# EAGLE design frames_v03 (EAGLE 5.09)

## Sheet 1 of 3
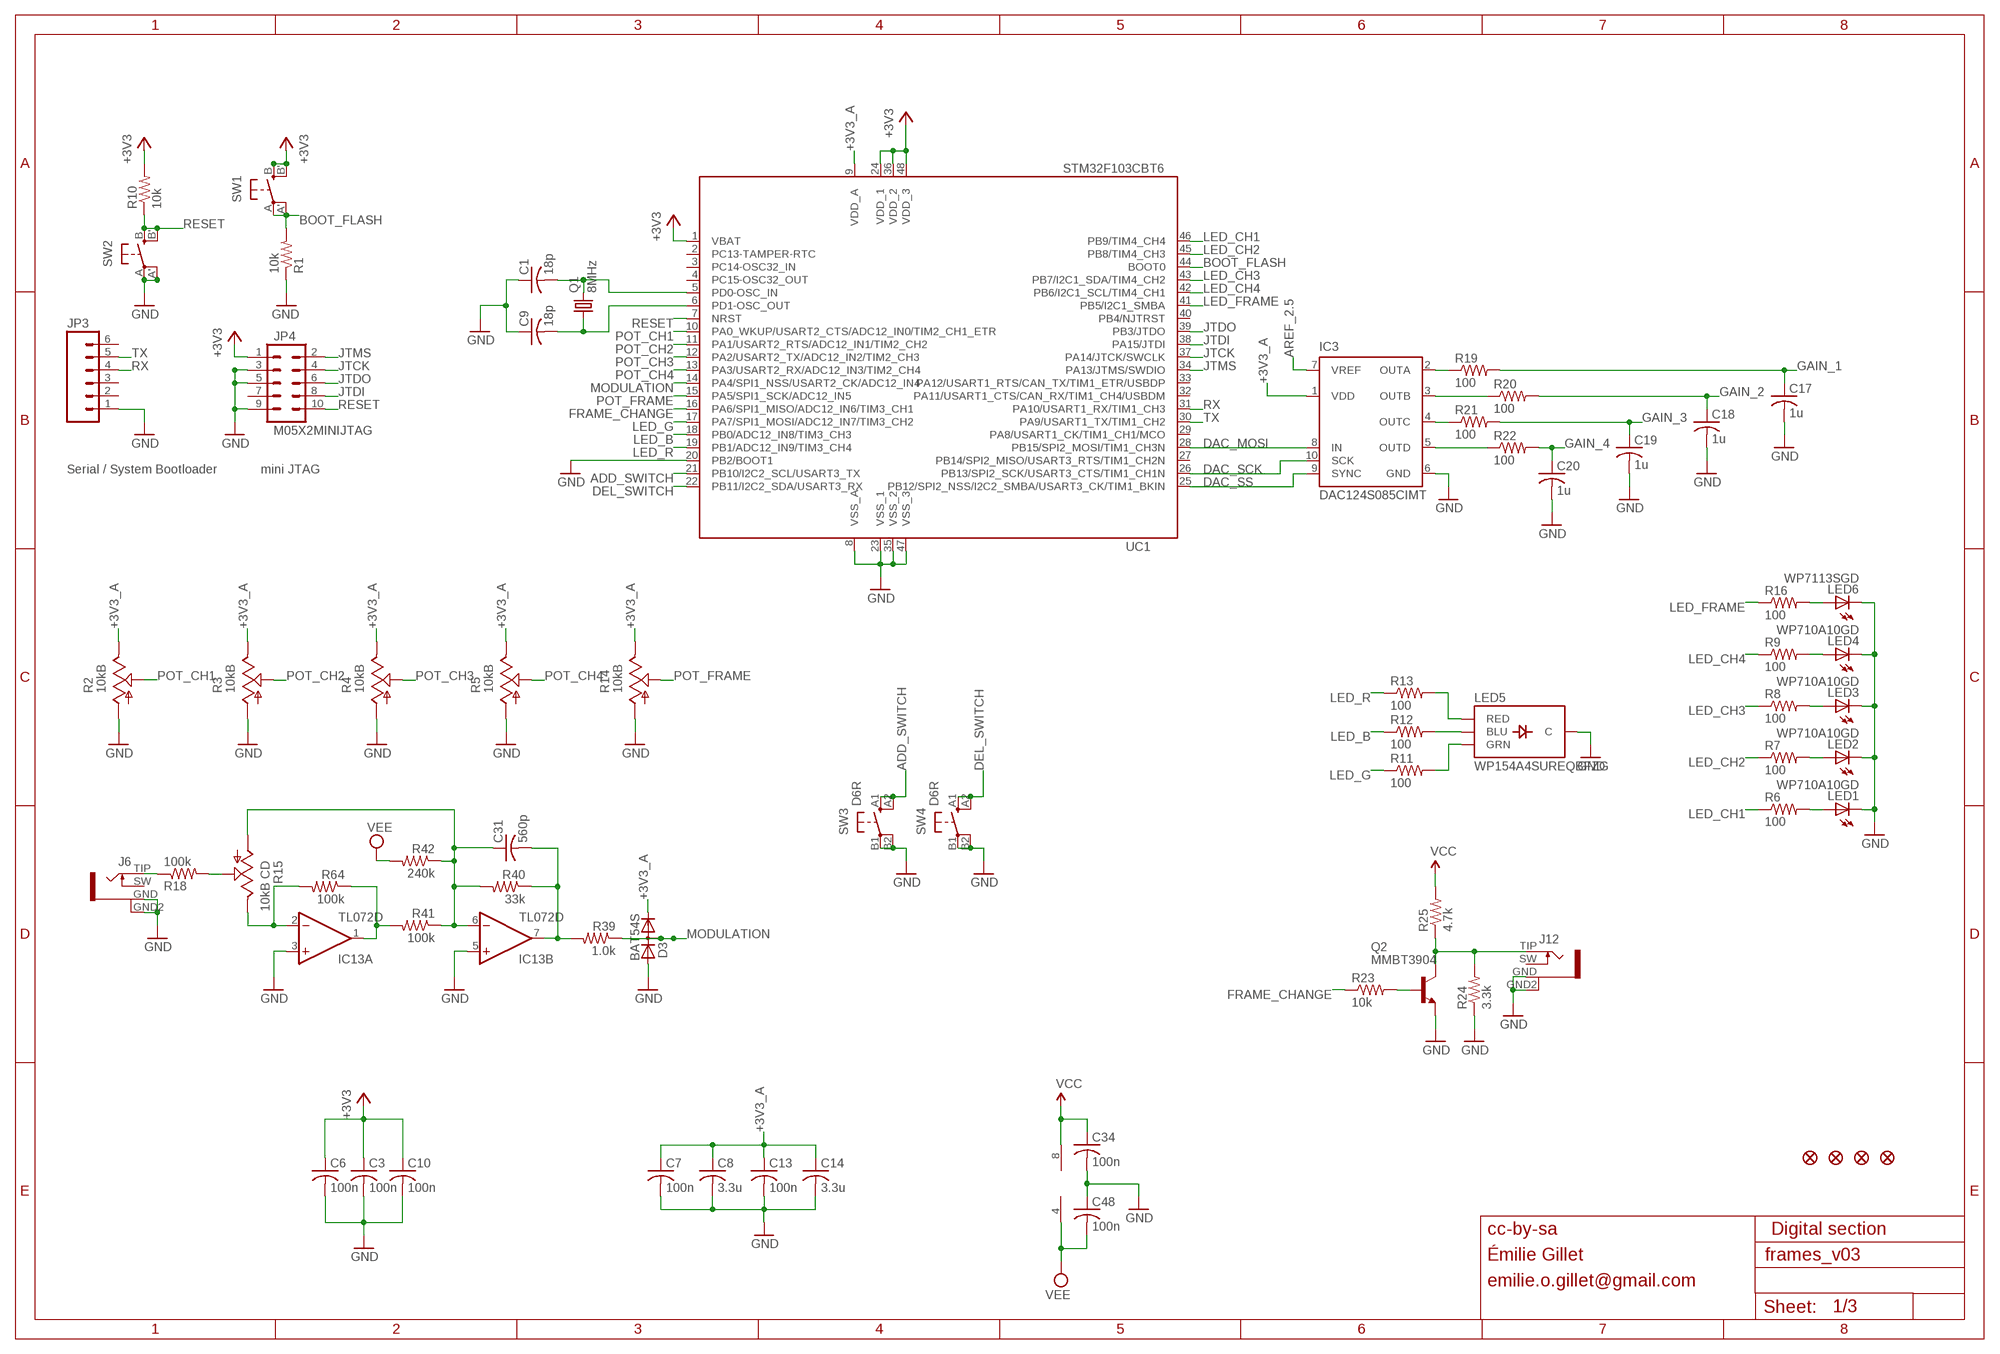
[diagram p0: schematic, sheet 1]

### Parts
C1  18p  C-USC0603  [C0603]
C3  100n  C-USC0603  [C0603]
C6  100n  C-USC0603  [C0603]
C7  100n  C-USC0603  [C0603]
C8  3.3u  C-USC0603  [C0603]
C9  18p  C-USC0603  [C0603]
C10  100n  C-USC0603  [C0603]
C13  100n  C-USC0603  [C0603]
C14  3.3u  C-USC0603  [C0603]
C17  1u  C-USC0603  [C0603]
C18  1u  C-USC0603  [C0603]
C19  1u  C-USC0603  [C0603]
C20  1u  C-USC0603  [C0603]
C31  560p  C-USC0603  [C0603]
C34  100n  C-USC0603  [C0603]
C48  100n  C-USC0603  [C0603]
D3  BAT54S  DIODE_2CACA-SOT23  [SOT23]
F1  FIDUCIAL1X2  [FIDUCIAL-1X2]
F2  FIDUCIAL1X2  [FIDUCIAL-1X2]
F3  FIDUCIAL1X2  [FIDUCIAL-1X2]
F4  FIDUCIAL1X2  [FIDUCIAL-1X2]
IC3  DAC124S085CIMT  [MSOP10]
IC13  TL072D  [SO08]
J6  PJ301WQP  [WQP_PJ_301BM]
J12  PJ301WQP  [WQP_PJ_301BM]
JP3  M06SIP  [1X06]
JP4  M05X2MINIJTAG  [2X5-1.27]
LED1  WP710A10GD  LED3MM  [LED3MM]
LED2  WP710A10GD  LED3MM  [LED3MM]
LED3  WP710A10GD  LED3MM  [LED3MM]
LED4  WP710A10GD  LED3MM  [LED3MM]
LED5  WP154A4SUREQBFZG  LED-TRICOLOR-THROUGHHOLE  [LED-TRICOLOR-THROUGHHOLE]
LED6  WP7113SGD  LED5MM  [LED5MM]
Q1  8MHz  CRYSTALHC49UP  [HC49UP]
Q2  MMBT3904  MMBT3904LT1-NPN-SOT23-BEC  [SOT23-BEC]
R1  10k  R-US_R0603  [R0603]
R2  10kB  POT_USVERTICAL_PS  [ALPS_POT_VERTICAL_PS]
R3  10kB  POT_USVERTICAL_PS  [ALPS_POT_VERTICAL_PS]
R4  10kB  POT_USVERTICAL_PS  [ALPS_POT_VERTICAL_PS]
R5  10kB  POT_USVERTICAL_PS  [ALPS_POT_VERTICAL_PS]
R6  100  R-US_R0603  [R0603]
R7  100  R-US_R0603  [R0603]
R8  100  R-US_R0603  [R0603]
R9  100  R-US_R0603  [R0603]
R10  10k  R-US_R0603  [R0603]
R11  100  R-US_R0603  [R0603]
R12  100  R-US_R0603  [R0603]
R13  100  R-US_R0603  [R0603]
R14  10kB  POT_USVERTICAL_PS  [ALPS_POT_VERTICAL_PS]
R15  10kB CD  POT_USVERTICAL_PS  [ALPS_POT_VERTICAL_PS]
R16  100  R-US_R0603  [R0603]
R18  100k  R-US_R0603  [R0603]
R19  100  R-US_R0603  [R0603]
R20  100  R-US_R0603  [R0603]
R21  100  R-US_R0603  [R0603]
R22  100  R-US_R0603  [R0603]
R23  10k  R-US_R0603  [R0603]
R24  3.3k  R-US_R0603  [R0603]
R25  4.7k  R-US_R0603  [R0603]
R39  1.0k  R-US_R0603  [R0603]
R40  33k  R-US_R0603  [R0603]
R41  100k  R-US_R0603  [R0603]
R42  240k  R-US_R0603  [R0603]
R64  100k  R-US_R0603  [R0603]
SW1  EVQQ2  [EVQ-Q2]
SW2  EVQQ2  [EVQ-Q2]
SW3  D6R  [D6R]
SW4  D6R  [D6R]
UC1  STM32F103CBT6  STM32F103CB  [LQFP48]

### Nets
+3V3: C3.1 C6.1 C10.1 JP4.1 R10.2 SW1.B'(S1) SW1.B(S) UC1.1(VBAT) UC1.24(VDD_1) UC1.36(VDD_2) UC1.48(VDD_3) ; also sheet 3
+3V3_A: C7.1 C8.1 C13.1 C14.1 D3.2(C) IC3.1(VDD) R2.P$1(E) R3.P$1(E) R4.P$1(E) R5.P$1(E) R14.P$1(E) UC1.9(VDD_A) ; also sheet 3
ADD_SWITCH: SW3.A1(S) SW3.A2(S1) UC1.21(PB10/I2C2_SCL/USART3_TX)
AREF_2.5: IC3.7(VREF) ; also sheet 3
BOOT_FLASH: R1.2 SW1.A'(P1) SW1.A(P) UC1.44(BOOT0)
DAC_MOSI: IC3.8(IN) UC1.28(PB15/SPI2_MOSI/TIM1_CH3N)
DAC_SCK: IC3.10(SCK) UC1.26(PB13/SPI2_SCK/USART3_CTS/TIM1_CH1N)
DAC_SS: IC3.9(SYNC) UC1.25(PB12/SPI2_NSS/I2C2_SMBA/USART3_CK/TIM1_BKIN)
DEL_SWITCH: SW4.A1(S) SW4.A2(S1) UC1.22(PB11/I2C2_SDA/USART3_RX)
FRAME_CHANGE: R23.1 UC1.16(PA6/SPI1_MISO/ADC12_IN6/TIM3_CH1)
GAIN_1: C17.1 R19.2 ; also sheet 2
GAIN_2: C18.1 R20.2 ; also sheet 2
GAIN_3: C19.1 R21.2 ; also sheet 2
GAIN_4: C20.1 R22.2 ; also sheet 2
GATE2_LED: LED3.A R8.2
GATE3_LED: LED2.A R7.2
GATE4_LED: LED1.A R6.2
GND: C1.1 C3.2 C6.2 C7.2 C8.2 C9.1 C10.2 C13.2 C14.2 C17.2 C18.2 C19.2 C20.2 C34.2 C48.1 D3.1(A) IC3.6(GND) IC13.3(A:+IN) IC13.5(B:+IN) J6.GND J6.GND2 J12.GND J12.GND2 JP3.1 JP4.3 JP4.5 JP4.9 LED1.K(C) LED2.K(C) LED3.K(C) LED4.K(C) LED5.GND(C) LED6.K(C) Q2.E R1.1 R2.P$3(A) R3.P$3(A) R4.P$3(A) R5.P$3(A) R14.P$3(A) R24.1 SW2.A'(P1) SW2.A(P) SW3.B1(P) SW3.B2(P1) SW4.B1(P) SW4.B2(P1) UC1.8(VSS_A) UC1.20(PB2/BOOT1) UC1.23(VSS_1) UC1.35(VSS_2) UC1.47(VSS_3) ; also sheet 2,3
JTCK: JP4.4 UC1.37(PA14/JTCK/SWCLK)
JTDI: JP4.8 UC1.38(PA15/JTDI)
JTDO: JP4.6 UC1.39(PB3/JTDO)
JTMS: JP4.2 UC1.34(PA13/JTMS/SWDIO)
LED_B: R12.1 UC1.18(PB0/ADC12_IN8/TIM3_CH3)
LED_CH1: R6.1 UC1.46(PB9/TIM4_CH4)
LED_CH2: R7.1 UC1.45(PB8/TIM4_CH3)
LED_CH3: R8.1 UC1.43(PB7/I2C1_SDA/TIM4_CH2)
LED_CH4: R9.1 UC1.42(PB6/I2C1_SCL/TIM4_CH1)
LED_FRAME: R16.1 UC1.41(PB5/I2C1_SMBA)
LED_G: R11.1 UC1.17(PA7/SPI1_MOSI/ADC12_IN7/TIM3_CH2)
LED_R: R13.1 UC1.19(PB1/ADC12_IN9/TIM3_CH4)
MODULATION: D3.3(AC) R39.1 UC1.14(PA4/SPI1_NSS/USART2_CK/ADC12_IN4)
N$1: IC13.2(A:-IN) R15.P$1(E) R64.2
N$5: R15.P$2(S) R18.2
N$6: LED4.A R9.2
N$7: C1.2 Q1.2 UC1.5(PD0-OSC_IN)
N$8: C9.2 Q1.1 UC1.6(PD1-OSC_OUT)
N$9: IC13.1(A:OUT) R41.2 R64.1
N$11: J6.TIP R18.1
N$13: C31.2 IC13.7(B:OUT) R39.2 R40.1
N$14: C31.1 IC13.6(B:-IN) R15.P$3(A) R40.2 R41.1 R42.1
N$25: LED6.A R16.2
N$35: LED5.RED R13.2
N$36: LED5.BLU R12.2
N$37: LED5.GRN R11.2
N$39: IC3.2(OUTA) R19.1
N$41: IC3.3(OUTB) R20.1
N$43: IC3.4(OUTC) R21.1
N$44: J12.TIP Q2.C R24.2 R25.1
N$45: IC3.5(OUTD) R22.1
N$47: Q2.B R23.2
POT_CH1: R2.P$2(S) UC1.10(PA0_WKUP/USART2_CTS/ADC12_IN0/TIM2_CH1_ETR)
POT_CH2: R3.P$2(S) UC1.11(PA1/USART2_RTS/ADC12_IN1/TIM2_CH2)
POT_CH3: R4.P$2(S) UC1.12(PA2/USART2_TX/ADC12_IN2/TIM2_CH3)
POT_CH4: R5.P$2(S) UC1.13(PA3/USART2_RX/ADC12_IN3/TIM2_CH4)
POT_FRAME: R14.P$2(S) UC1.15(PA5/SPI1_SCK/ADC12_IN5)
RESET: JP4.10 R10.1 SW2.B'(S1) SW2.B(S) UC1.7(NRST)
RX: JP3.4 UC1.31(PA10/USART1_RX/TIM1_CH3)
TX: JP3.5 UC1.30(PA9/USART1_TX/TIM1_CH2)
VCC: C34.1 IC13.8(P:V+) R25.2 ; also sheet 2,3
VEE: C48.2 IC13.4(P:V-) R42.2 ; also sheet 2,3
Unconnected: J6.SW J12.SW JP3.2 JP3.3 JP3.6 JP4.7 UC1.2(PC13-TAMPER-RTC) UC1.3(PC14-OSC32_IN) UC1.4(PC15-OSC32_OUT) UC1.27(PB14/SPI2_MISO/USART3_RTS/TIM1_CH2N) UC1.29(PA8/USART1_CK/TIM1_CH1/MCO) UC1.32(PA11/USART1_CTS/CAN_RX/TIM1_CH4/USBDM) UC1.33(PA12/USART1_RTS/CAN_TX/TIM1_ETR/USBDP) UC1.40(PB4/NJTRST)

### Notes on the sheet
- Serial / System Bootloader | mini JTAG
- cc-by-sa | Digital section
- Émilie Gillet
- emilie.o.gillet@gmail.com

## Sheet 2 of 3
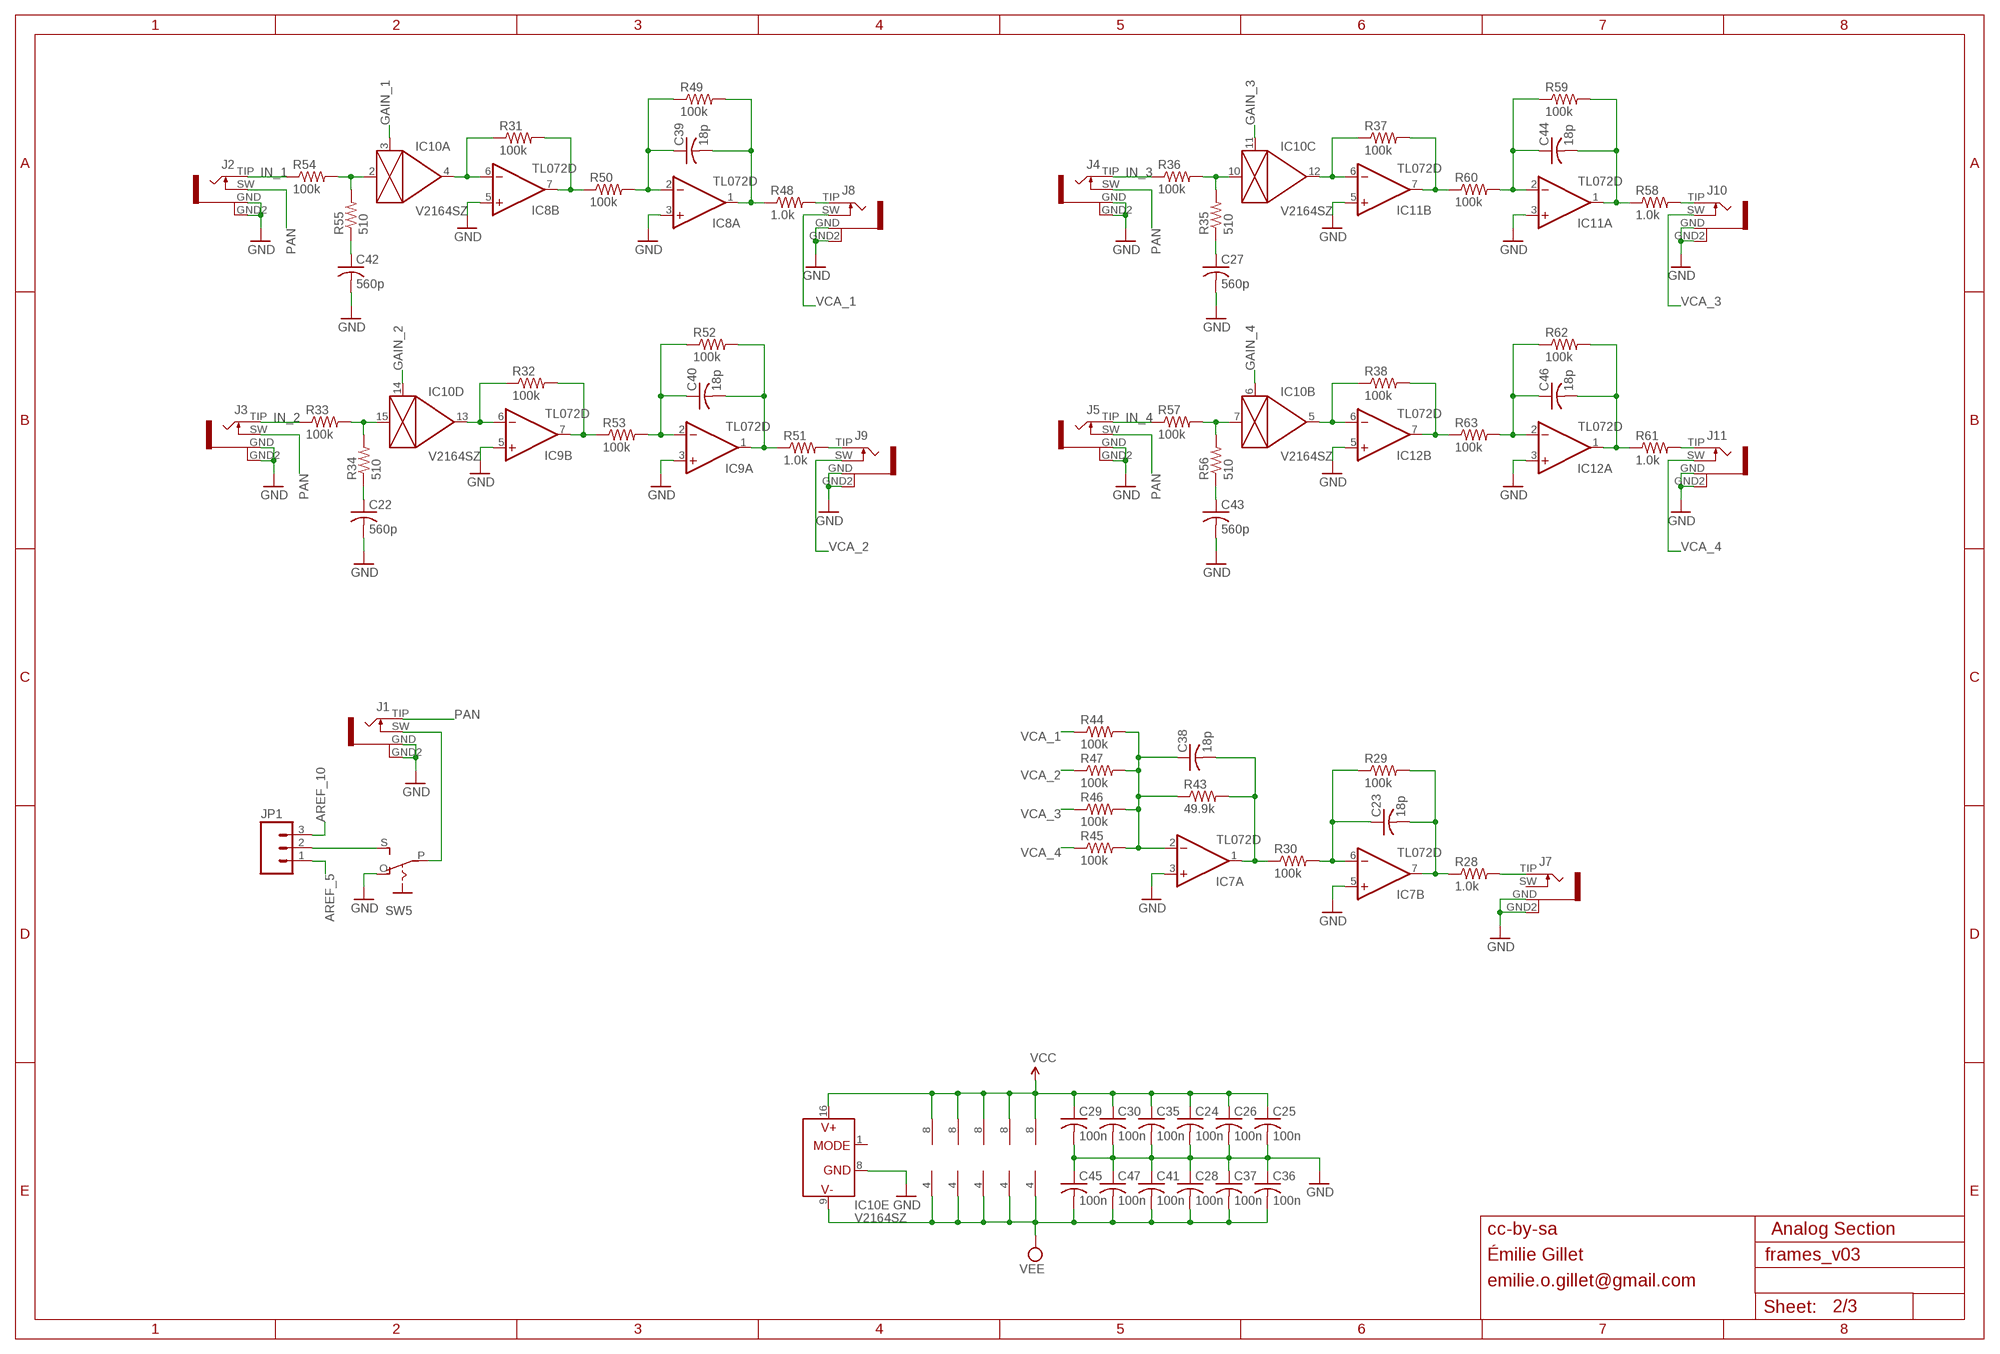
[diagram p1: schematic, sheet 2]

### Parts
C22  560p  C-USC0603  [C0603]
C23  18p  C-USC0603  [C0603]
C24  100n  C-USC0603  [C0603]
C25  100n  C-USC0603  [C0603]
C26  100n  C-USC0603  [C0603]
C27  560p  C-USC0603  [C0603]
C28  100n  C-USC0603  [C0603]
C29  100n  C-USC0603  [C0603]
C30  100n  C-USC0603  [C0603]
C35  100n  C-USC0603  [C0603]
C36  100n  C-USC0603  [C0603]
C37  100n  C-USC0603  [C0603]
C38  18p  C-USC0603  [C0603]
C39  18p  C-USC0603  [C0603]
C40  18p  C-USC0603  [C0603]
C41  100n  C-USC0603  [C0603]
C42  560p  C-USC0603  [C0603]
C43  560p  C-USC0603  [C0603]
C44  18p  C-USC0603  [C0603]
C45  100n  C-USC0603  [C0603]
C46  18p  C-USC0603  [C0603]
C47  100n  C-USC0603  [C0603]
IC7  TL072D  [SO08]
IC8  TL072D  [SO08]
IC9  TL072D  [SO08]
IC10  V2164SZ  SSM2164S  [SOIC16N]
IC11  TL072D  [SO08]
IC12  TL072D  [SO08]
J1  PJ301WQP  [WQP_PJ_301BM]
J2  PJ301WQP  [WQP_PJ_301BM]
J3  PJ301WQP  [WQP_PJ_301BM]
J4  PJ301WQP  [WQP_PJ_301BM]
J5  PJ301WQP  [WQP_PJ_301BM]
J7  PJ301WQP  [WQP_PJ_301BM]
J8  PJ301WQP  [WQP_PJ_301BM]
J9  PJ301WQP  [WQP_PJ_301BM]
J10  PJ301WQP  [WQP_PJ_301BM]
J11  PJ301WQP  [WQP_PJ_301BM]
JP1  M03PTH  [1X03]
R28  1.0k  R-US_R0603  [R0603]
R29  100k  R-US_R0603  [R0603]
R30  100k  R-US_R0603  [R0603]
R31  100k  R-US_R0603  [R0603]
R32  100k  R-US_R0603  [R0603]
R33  100k  R-US_R0603  [R0603]
R34  510  R-US_R0603  [R0603]
R35  510  R-US_R0603  [R0603]
R36  100k  R-US_R0603  [R0603]
R37  100k  R-US_R0603  [R0603]
R38  100k  R-US_R0603  [R0603]
R43  49.9k  R-US_R0603  [R0603]
R44  100k  R-US_R0603  [R0603]
R45  100k  R-US_R0603  [R0603]
R46  100k  R-US_R0603  [R0603]
R47  100k  R-US_R0603  [R0603]
R48  1.0k  R-US_R0603  [R0603]
R49  100k  R-US_R0603  [R0603]
R50  100k  R-US_R0603  [R0603]
R51  1.0k  R-US_R0603  [R0603]
R52  100k  R-US_R0603  [R0603]
R53  100k  R-US_R0603  [R0603]
R54  100k  R-US_R0603  [R0603]
R55  510  R-US_R0603  [R0603]
R56  510  R-US_R0603  [R0603]
R57  100k  R-US_R0603  [R0603]
R58  1.0k  R-US_R0603  [R0603]
R59  100k  R-US_R0603  [R0603]
R60  100k  R-US_R0603  [R0603]
R61  1.0k  R-US_R0603  [R0603]
R62  100k  R-US_R0603  [R0603]
R63  100k  R-US_R0603  [R0603]
SW5  S-ON-ONSMALL_SLIDE  [ES_100SP1T6B11M2QEH_SMALL]

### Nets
AREF_5: JP1.1 ; also sheet 3
AREF_10: JP1.3 ; also sheet 3
FB_CURRENT: IC10.2(A:IN) R54.2 R55.2
FB_CURRENT1: IC10.15(D:IN) R33.2 R34.2
FB_CURRENT2: IC10.10(C:IN) R35.2 R36.2
FB_CURRENT3: IC10.7(B:IN) R56.2 R57.2
GAIN_1: IC10.3(A:CTRL) ; also sheet 1
GAIN_2: IC10.14(D:CTRL) ; also sheet 1
GAIN_3: IC10.11(C:CTRL) ; also sheet 1
GAIN_4: IC10.6(B:CTRL) ; also sheet 1
GND: C22.2 C24.2 C25.2 C26.2 C27.2 C28.1 C29.2 C30.2 C35.2 C36.1 C37.1 C41.1 C42.2 C43.2 C45.1 C47.1 IC7.3(A:+IN) IC7.5(B:+IN) IC8.3(A:+IN) IC8.5(B:+IN) IC9.3(A:+IN) IC9.5(B:+IN) IC10.8(E:GND) IC11.3(A:+IN) IC11.5(B:+IN) IC12.3(A:+IN) IC12.5(B:+IN) J1.GND J1.GND2 J2.GND J2.GND2 J3.GND J3.GND2 J4.GND J4.GND2 J5.GND J5.GND2 J7.GND J7.GND2 J8.GND J8.GND2 J9.GND J9.GND2 J10.GND J10.GND2 J11.GND J11.GND2 SW5.O ; also sheet 1,3
IN_1: J2.TIP R54.1
IN_2: J3.TIP R33.1
IN_3: J4.TIP R36.1
IN_4: J5.TIP R57.1
N$2: C42.1 R55.1
N$3: J7.TIP R28.2
N$4: IC9.7(B:OUT) R32.2 R53.1
N$10: C27.1 R35.1
N$12: IC8.6(B:-IN) IC10.4(A:OUT) R31.1
N$15: C39.1 IC8.2(A:-IN) R49.1 R50.2
N$16: C39.2 IC8.1(A:OUT) R48.1 R49.2
N$17: C23.2 IC7.7(B:OUT) R28.1 R29.2
N$18: C22.1 R34.1
N$19: C38.1 IC7.2(A:-IN) R43.1 R44.2 R45.2 R46.2 R47.2
N$20: IC9.6(B:-IN) IC10.13(D:OUT) R32.1
N$21: C23.1 IC7.6(B:-IN) R29.1 R30.2
N$22: C40.1 IC9.2(A:-IN) R52.1 R53.2
N$23: C40.2 IC9.1(A:OUT) R51.1 R52.2
N$24: IC10.12(C:OUT) IC11.6(B:-IN) R37.1
N$26: C44.1 IC11.2(A:-IN) R59.1 R60.2
N$27: C44.2 IC11.1(A:OUT) R58.1 R59.2
N$28: C43.1 R56.1
N$29: C38.2 IC7.1(A:OUT) R30.1 R43.2
N$30: IC10.5(B:OUT) IC12.6(B:-IN) R38.1
N$32: C46.1 IC12.2(A:-IN) R62.1 R63.2
N$33: C46.2 IC12.1(A:OUT) R61.1 R62.2
N$34: J1.SW SW5.P
N$40: J8.TIP R48.2
N$42: JP1.2 SW5.S
N$48: IC12.7(B:OUT) R38.2 R63.1
N$49: J9.TIP R51.2
N$50: J11.TIP R61.2
N$51: J10.TIP R58.2
PAN: J1.TIP J2.SW J3.SW J4.SW J5.SW
VCA0_1: IC8.7(B:OUT) R31.2 R50.1
VCA0_3: IC11.7(B:OUT) R37.2 R60.1
VCA_1: J8.SW R44.1
VCA_2: J9.SW R47.1
VCA_3: J10.SW R46.1
VCA_4: J11.SW R45.1
VCC: C24.1 C25.1 C26.1 C29.1 C30.1 C35.1 IC7.8(P:V+) IC8.8(P:V+) IC9.8(P:V+) IC10.16(E:V+) IC11.8(P:V+) IC12.8(P:V+) ; also sheet 1,3
VEE: C28.2 C36.2 C37.2 C41.2 C45.2 C47.2 IC7.4(P:V-) IC8.4(P:V-) IC9.4(P:V-) IC10.9(E:V-) IC11.4(P:V-) IC12.4(P:V-) ; also sheet 1,3
Unconnected: IC10.1(E:MODE) J7.SW

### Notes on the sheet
- cc-by-sa | Analog Section
- Émilie Gillet
- emilie.o.gillet@gmail.com

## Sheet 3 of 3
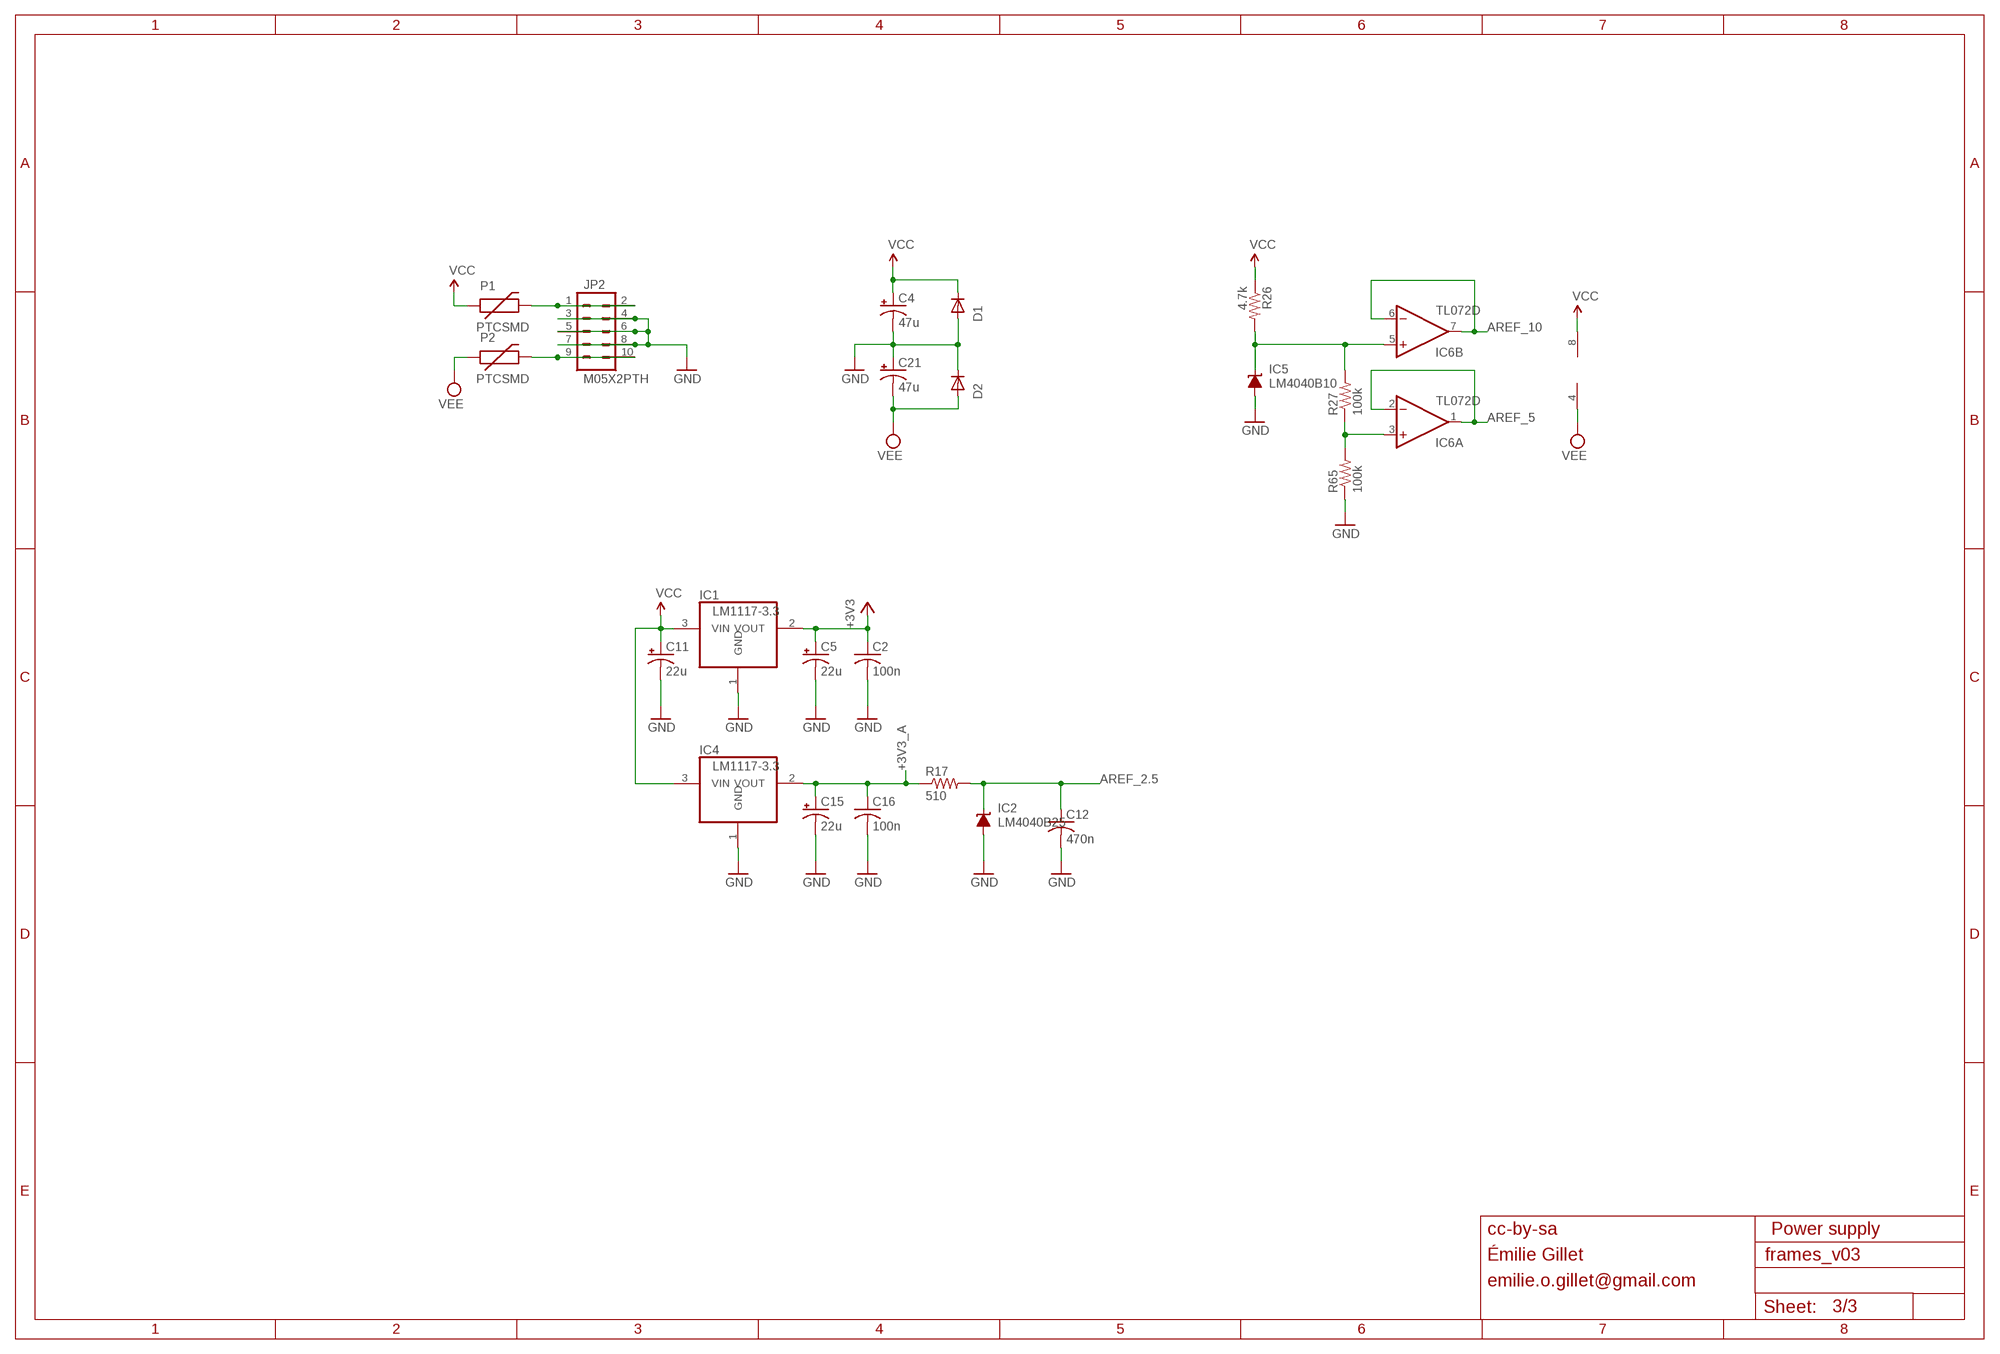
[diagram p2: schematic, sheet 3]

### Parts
C2  100n  C-USC0603  [C0603]
C4  47u  CPOL-USD  [PANASONIC_D]
C5  22u  CPOL-USC  [PANASONIC_C]
C11  22u  CPOL-USC  [PANASONIC_C]
C12  470n  C-USC0603  [C0603]
C15  22u  CPOL-USC  [PANASONIC_C]
C16  100n  C-USC0603  [C0603]
C21  47u  CPOL-USD  [PANASONIC_D]
D1  1N5819HW  DIODE-SOD123  [SOD123]
D2  1N5819HW  DIODE-SOD123  [SOD123]
IC1  LM1117-3.3  REG1117  [SOT223]
IC2  LM4040B25  LM4041B12DBZ  [DBZ_R-PDSO-G3]
IC4  LM1117-3.3  REG1117  [SOT223]
IC5  LM4040B10  LM4041B12DBZ  [DBZ_R-PDSO-G3]
IC6  TL072D  [SO08]
JP2  M05X2PTH  [AVR_ICSP]
P1  PTCSMD  [PTC-1206]
P2  PTCSMD  [PTC-1206]
R17  510  R-US_R0603  [R0603]
R26  4.7k  R-US_R0603  [R0603]
R27  100k  R-US_R0603  [R0603]
R65  100k  R-US_R0603  [R0603]

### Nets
+3V3: C2.1 C5.+ IC1.2(VOUT) ; also sheet 1
+3V3_A: C15.+ C16.1 IC4.2(VOUT) R17.1 ; also sheet 1
AREF_2.5: C12.1 IC2.1(C) R17.2 ; also sheet 1
AREF_5: IC6.1(A:OUT) IC6.2(A:-IN) ; also sheet 2
AREF_10: IC6.6(B:-IN) IC6.7(B:OUT) ; also sheet 2
AREF_10_0: IC5.1(C) IC6.5(B:+IN) R26.2 R27.2
GND: C2.2 C4.- C5.- C11.- C12.2 C15.- C16.2 C21.+ D1.A D2.C IC1.1(GND) IC2.2(A) IC4.1(GND) IC5.2(A) JP2.3 JP2.4 JP2.5 JP2.6 JP2.7 JP2.8 R65.1 ; also sheet 1,2
N$31: IC6.3(A:+IN) R27.1 R65.2
N$56: JP2.1 JP2.2 P1.2
N$64: JP2.9 JP2.10 P2.2
VCC: C4.+ C11.+ D1.C IC1.3(VIN) IC4.3(VIN) IC6.8(P:V+) P1.1 R26.1 ; also sheet 1,2
VEE: C21.- D2.A IC6.4(P:V-) P2.1 ; also sheet 1,2

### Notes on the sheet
- cc-by-sa | Power supply
- Émilie Gillet
- emilie.o.gillet@gmail.com

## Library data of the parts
C1-C3 C6-C10 C12-C14 C16-C20 C22-C31 C34-C48 = rcl:C-US: CAPACITOR, American symbol
C4 C5 C11 C15 C21 = rcl:CPOL-US: POLARIZED CAPACITOR, American symbol
D1 D2 = diode:DIODE-: DIODE
D3 = diode:DIODE_2CACA-: 2 Diodes - Cathode-Anode|Cathode-Anode
F1-F4 = SparkFun:FIDUCIAL: Fiducial Alignment Points
IC1 IC4 = og-vreg:REG1117: 800mA and 1A Low Dropout (LDO) Positive Regulator 1.8V, 2.5V, 2.85V, 3.3V, 5V, and Adj
IC2 IC5 = texas:LM4041: PRECISION MICROPOWER SHUNT VOLTAGE REFERENCE
IC3 = og-dac:DAC124S085CIMT
IC6 = gm-ics:TL072: OP AMP
IC7-IC9 IC11-IC13 = og-linear:TL072: OP AMP
IC10 = ssm2164:SSM2164
J1-J12 = og-pj301:PJ301
JP1 = SparkFun:M03: Header 3 Standard 3-pin 0.1" header. Use with straight break away headers (SKU : PRT-00116), right angle break away headers (PRT-00553), swiss pins (PRT-00743), machine pins (PRT-00117), and female headers (PRT-00115). Molex polarized connector foot print use with SKU : PRT-08232 with associated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
JP2 JP4 = og-header:M05X2: Header 5x2 Standard 10-pin dual row 0.1" header. Commonly used with AVR-ISP. Use with Spark Fun Electronics SKU: PRT-00778
JP3 = SparkFun:M06: Header 6 Standard 6-pin 0.1" header. Use with straight break away headers (SKU : PRT-00116), right angle break away headers (PRT-00553), swiss pins (PRT-00743), machine pins (PRT-00117), and female headers (PRT-00115). Molex polarized connector foot print use with SKU : PRT-08094 with associated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
LED1-LED4 LED6 = led:LED: LED
LED5 = og-leds:LED-TRICOLOR-THROUGHHOLE
P1 P2 = SparkFun:PTC: Resettable Fuse PTC
Q1 = crystal:CRYSTAL: CRYSTAL
Q2 = transistor:*-NPN-: NPN Transistror BF959 corrected 2008.03.06
R1 R6-R13 R16-R65 = rcl:R-US_: RESISTOR, American symbol
R2-R5 R14 R15 = pot-alps:POT_US
SW1 SW2 = adafruit:EVQQ2: SMT 6mm switch, EVQQ2 series http://www.ladyada.net/library/eagle
SW3 SW4 = og-switch:D6R: C&K D6R
SW5 = og-switch:S-ON-ON: On-on Switch
UC1 = stm32:STM32F103CB

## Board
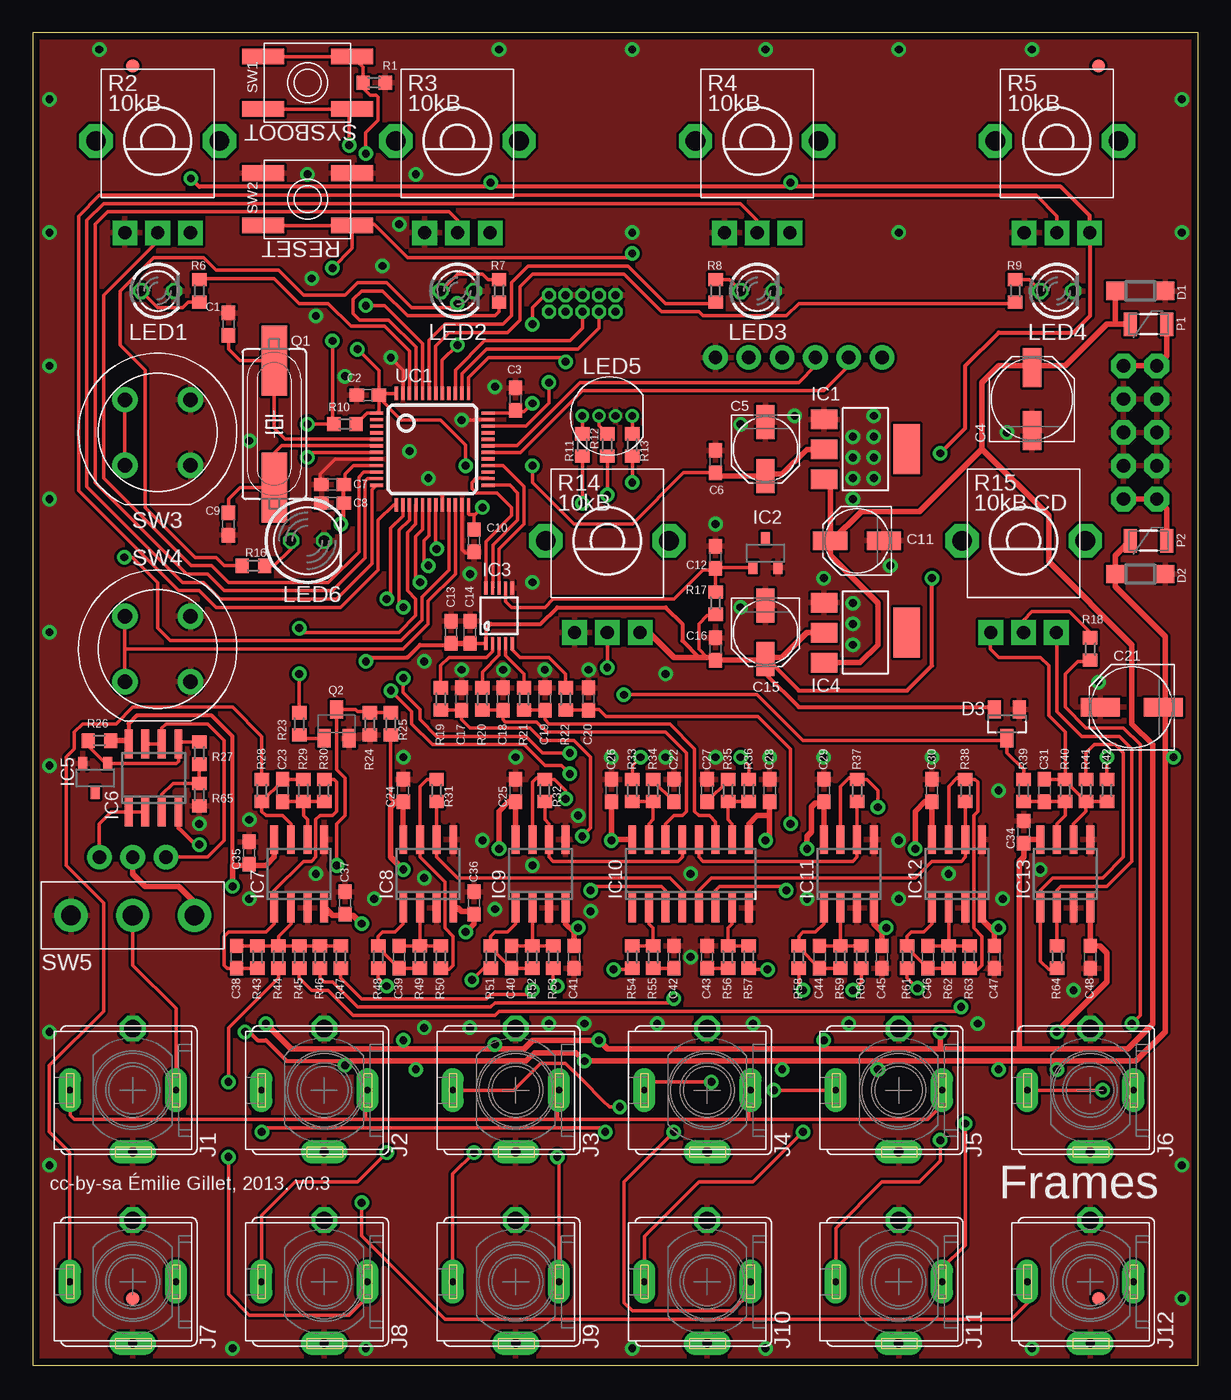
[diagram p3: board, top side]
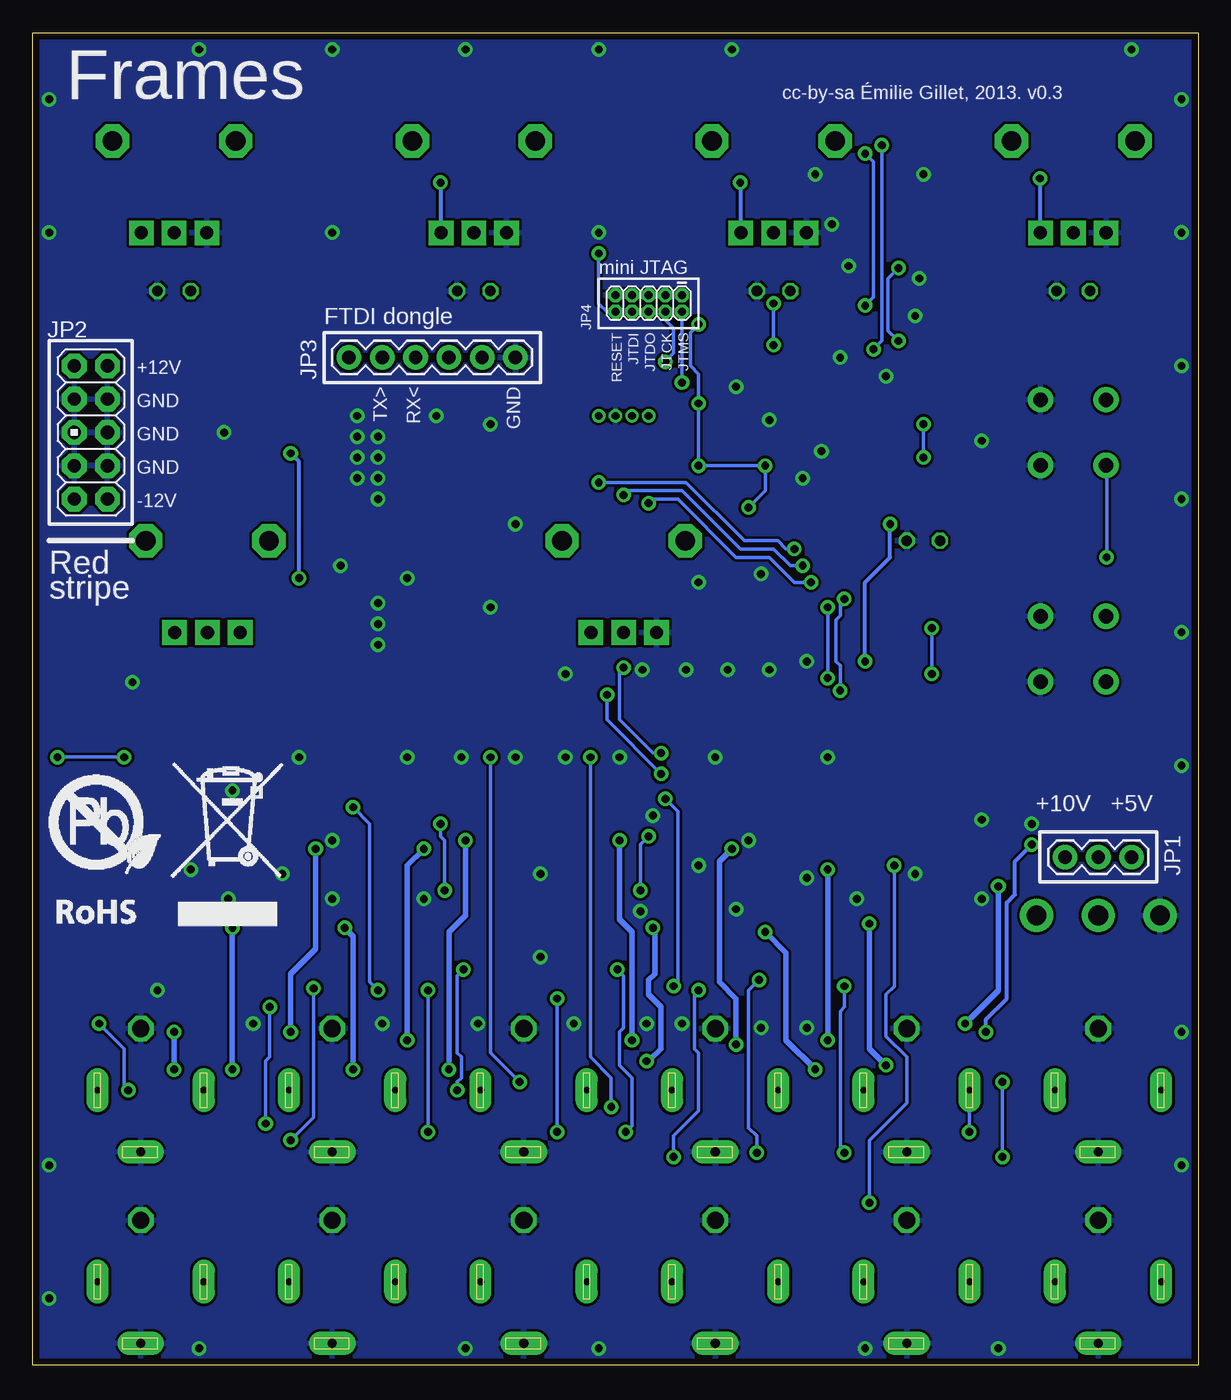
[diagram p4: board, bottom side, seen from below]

Size 88.88 x 101.6 mm. Coordinates in mm from the lower left corner, seen from the top.
Outline: 0,0 88.88,0 88.88,101.6 0,101.6 0,0
Copper layers (1*16): Top 0.035mm / dielectric 1.5mm / Bottom 0.035mm
Design rules "PCBCart-Standard": minimum track width 8mil, minimum drill 0.4mm, track to track 8mil, track to pad 8mil, pad to pad 8mil, via to via 8mil, smd to smd 8mil, copper to edge 20mil, drill to drill 8mil, minimum pad ring 8mil, minimum via ring 10mil, stop-mask expansion 3mil, vias tented up to drill 25mil, thermal gap 8mil

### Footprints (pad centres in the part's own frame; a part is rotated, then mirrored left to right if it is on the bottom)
C0603 = smd 1.1 x 1: 1 -0.85,0; 2 0.85,0
PANASONIC_D = smd 3 x 1.4: + 2.4,0; - -2.4,0
PANASONIC_C = smd 2.6 x 1.4: + 2.05,0; - -2.05,0
SOD123 = smd 1.4 x 1.4: A 1.9,0; C -1.9,0
SOT23 = smd 1 x 1.4: 1 -0.95,-1.1; 2 0.95,-1.1; 3 0,1.1
FIDUCIAL-1X2 = smd 1 x 1: 1 0,0
SOT223 = smd 1.499 x 2.007: 1 -2.261,-3.15; 2 0.025,-3.15; 3 2.311,-3.15 | smd 3.81 x 2.007: 4 0,3.15
DBZ_R-PDSO-G3 = smd 0.7 x 1: 1 -0.95,-1.1; 2 0.95,-1.1; 3 0,1.1
MSOP10 = smd 0.25 x 1: 1 -1,-2.113; 2 -0.5,-2.113; 3 0,-2.113; 4 0.5,-2.113; 5 1,-2.113; 6 1,2.113; 7 0.5,2.113; 8 0,2.113; 9 -0.5,2.113; 10 -1,2.113
SO08 = smd 0.6 x 2.2: 1 -1.905,-2.6; 2 -0.635,-2.6; 3 0.635,-2.6; 4 1.905,-2.6; 5 1.905,2.6; 6 0.635,2.6; 7 -0.635,2.6; 8 -1.905,2.6
SOIC16N = smd 0.6 x 2.2: 1 -4.445,-2.6; 2 -3.175,-2.6; 3 -1.905,-2.6; 4 -0.635,-2.6; 5 0.635,-2.6; 6 1.905,-2.6; 7 3.175,-2.6; 8 4.445,-2.6; 9 4.445,2.6; 10 3.175,2.6; 11 1.905,2.6; 12 0.635,2.6; 13 -0.635,2.6; 14 -1.905,2.6; 15 -3.175,2.6; 16 -4.445,2.6
WQP_PJ_301BM = drill 0.7 pad 1.778 long: GND -4.7,0 | drill 1.3 octagon: GND2 4.7,0 | drill 0.508 pad 1.676 long: SW 0,-3.3; TIP 0,4.8
1X03 = drill 1.016 pad 1.88 round: 1 0,0; 2 2.54,0; 3 5.08,0
AVR_ICSP = drill 1.016 pad 1.88 octagon: 1 -1.27,5.08; 2 1.27,5.08; 3 -1.27,2.54; 4 1.27,2.54; 5 -1.27,0; 6 1.27,0; 7 -1.27,-2.54; 8 1.27,-2.54; 9 -1.27,-5.08; 10 1.27,-5.08
1X06 = drill 1.016 pad 1.88 round: 1 0,0; 2 2.54,0; 3 5.08,0; 4 7.62,0; 5 10.16,0; 6 12.7,0
2X5-1.27 = drill 0.61 pad 1.067 octagon: 1 -1.27,3.81; 2 0,3.81; 3 -1.27,2.54; 4 0,2.54; 5 -1.27,1.27; 6 0,1.27; 7 -1.27,0; 8 0,0; 9 -1.27,-1.27; 10 0,-1.27
LED3MM = drill 0.813 octagon: A -1.27,0; K 1.27,0
LED-TRICOLOR-THROUGHHOLE = drill 0.6 round: BLU 0.635,0; GND -0.635,0; GRN 1.905,0; RED -1.905,0
LED5MM = drill 0.813 octagon: A -1.27,0; K 1.27,0
PTC-1206 = smd 1 x 1.8: 1 -1.4,0; 2 1.4,0
HC49UP = smd 5.334 x 1.93: 1 -4.826,0; 2 4.826,0
SOT23-BEC = smd 1 x 1.4: B -0.95,-1.1; C 0,1.1; E 0.95,-1.1
R0603 = smd 1 x 1.1: 1 -0.85,0; 2 0.85,0
ALPS_POT_VERTICAL_PS = drill 1 pad 1.88 square: P$1 -2.5,7; P$2 0,7; P$3 2.5,7 | drill 1.5 pad 2.54 octagon: P$4 -4.7,0; P$5 4.7,0
EVQ-Q2 = smd 3.2 x 1.2: A -3.4,-2; A' 3.4,-2; B -3.4,2; B' 3.4,2
D6R = drill 1.1 pad 1.93 round: A1 -2.5,2.5; A2 2.5,2.5; B1 -2.5,-2.5; B2 2.5,-2.5
ES_100SP1T6B11M2QEH_SMALL = drill 1.5 pad 2.54 round: O -4.699,0; P 0,0; S 4.699,0
LQFP48 = smd 0.254 x 1: 1 -2.75,-4.25; 2 -2.25,-4.25; 3 -1.75,-4.25; 4 -1.25,-4.25; 5 -0.75,-4.25; 6 -0.25,-4.25; 7 0.25,-4.25; 8 0.75,-4.25; 9 1.25,-4.25; 10 1.75,-4.25; 11 2.25,-4.25; 12 2.75,-4.25; 25 2.75,4.25; 26 2.25,4.25; 27 1.75,4.25; 28 1.25,4.25; 29 0.75,4.25; 30 0.25,4.25; 31 -0.25,4.25; 32 -0.75,4.25; 33 -1.25,4.25; 34 -1.75,4.25; 35 -2.25,4.25; 36 -2.75,4.25 | smd 1 x 0.254: 13 4.25,-2.75; 14 4.25,-2.25; 15 4.25,-1.75; 16 4.25,-1.25; 17 4.25,-0.75; 18 4.25,-0.25; 19 4.25,0.25; 20 4.25,0.75; 21 4.25,1.25; 22 4.25,1.75; 23 4.25,2.25; 24 4.25,2.75; 37 -4.25,2.75; 38 -4.25,2.25; 39 -4.25,1.75; 40 -4.25,1.25; 41 -4.25,0.75; 42 -4.25,0.25; 43 -4.25,-0.25; 44 -4.25,-0.75; 45 -4.25,-1.25; 46 -4.25,-1.75; 47 -4.25,-2.25; 48 -4.25,-2.75

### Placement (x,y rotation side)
C1  14.92,79.38 270 top
C2  25.56,73.98 180 top
C3  36.83,73.66 90 top
C4  76.2,73.66 90 top
C5  55.88,69.85 270 top
C6  52.07,68.9 90 top
C7  22.86,67.15 180 top
C8  22.86,65.72 180 top
C9  14.92,64.14 90 top
C10  33.66,62.87 270 top
C11  62.87,62.87 180 top
C12  52.07,61.59 90 top
C13  31.91,55.88 90 top
C14  33.34,55.88 90 top
C15  55.88,55.88 270 top
C16  52.07,54.61 90 top
C17  32.7,50.8 90 top
C18  35.88,50.8 90 top
C19  39.05,50.8 90 top
C20  42.39,50.8 90 top
C21  83.82,50.16 180 top
C22  48.9,43.82 90 top
C23  19.05,43.81 90 top
C24  28.26,43.81 90 top
C25  36.83,43.81 90 top
C26  44.13,43.81 90 top
C27  51.44,43.81 90 top
C28  56.2,43.81 270 top
C29  60.33,43.81 90 top
C30  68.58,43.81 90 top
C31  77.15,43.81 270 top
C34  75.56,40.64 90 top
C35  16.51,39.05 90 top
C36  33.66,35.24 270 top
C37  23.81,35.24 270 top
C38  15.56,31.11 270 top
C39  27.94,31.11 270 top
C40  36.51,31.11 270 top
C41  41.27,31.11 90 top
C42  48.9,31.11 90 top
C43  51.44,31.11 90 top
C44  60.01,31.11 270 top
C45  64.77,31.11 90 top
C46  68.26,31.11 270 top
C47  73.34,31.11 90 top
C48  80.64,31.11 90 top
D1  84.45,81.92 0 top
D2  84.45,60.33 180 top
D3  74.3,48.9 180 top
F1  7.62,99.06 0 top
F2  81.28,99.06 0 top
F3  7.62,5.08 0 top
F4  81.28,5.08 0 top
IC1  63.5,69.85 270 top
IC2  55.88,61.91 0 top
IC3  35.56,57.15 0 top
IC4  63.5,55.88 270 top
IC5  4.76,44.77 180 top
IC6  9.21,44.77 0 top
IC7  20.32,37.47 0 top
IC8  30.16,37.47 0 top
IC9  38.73,37.47 0 top
IC10  50.16,37.47 0 top
IC11  62.23,37.47 0 top
IC12  70.48,37.47 0 top
IC13  78.74,37.47 0 top
J1  7.62,20.95 90 top
J2  22.23,20.95 90 top
J3  36.83,20.95 90 top
J4  51.44,20.95 90 top
J5  66.04,20.95 90 top
J6  80.64,20.95 90 top
J7  7.62,6.35 90 top
J8  22.23,6.35 90 top
J9  36.83,6.35 90 top
J10  51.44,6.35 90 top
J11  66.04,6.35 90 top
J12  80.64,6.35 90 top
JP1  5.08,38.73 180 bottom
JP2  84.45,71.12 0 bottom
JP3  52.07,76.83 180 bottom
JP4  43.18,80.33 270 bottom
LED1  9.53,81.92 0 top
LED2  32.38,81.92 0 top
LED3  55.24,81.92 0 top
LED4  78.11,81.92 0 top
LED5  43.81,72.39 180 top
LED6  20.95,62.87 0 top
P1  85.09,79.38 0 top
P2  85.09,62.87 0 top
Q1  18.41,71.75 90 top
Q2  23.18,48.9 0 top
R1  26.04,97.79 180 top
R2  9.53,93.34 180 top
R3  32.38,93.34 180 top
R4  55.24,93.34 180 top
R5  78.11,93.34 180 top
R6  12.7,81.92 270 top
R7  35.56,81.92 90 top
R8  52.07,81.92 90 top
R9  74.93,81.92 90 top
R10  23.81,71.75 0 top
R11  41.91,70.17 90 top
R12  43.81,70.17 90 top
R13  45.72,70.17 90 top
R14  43.81,62.87 180 top
R15  75.56,62.87 180 top
R16  16.83,60.96 0 top
R17  52.07,58.1 90 top
R18  80.64,54.61 90 top
R19  31.11,50.8 270 top
R20  34.29,50.8 270 top
R21  37.47,50.8 270 top
R22  40.64,50.8 270 top
R23  20.32,48.9 270 top
R24  25.72,48.9 90 top
R25  27.3,48.9 270 top
R26  5.08,47.62 180 top
R27  12.7,46.67 90 top
R28  17.46,43.81 90 top
R29  20.64,43.81 90 top
R30  22.23,43.81 270 top
R31  30.8,43.81 90 top
R32  39.05,43.81 90 top
R33  45.72,43.81 270 top
R34  47.31,43.81 270 top
R35  53.02,43.81 270 top
R36  54.61,43.81 270 top
R37  62.87,43.81 90 top
R38  71.12,43.81 90 top
R39  75.56,43.81 270 top
R40  78.74,43.81 90 top
R41  80.33,43.81 90 top
R42  81.92,43.81 90 top
R43  17.14,31.11 270 top
R44  18.73,31.11 90 top
R45  20.32,31.11 90 top
R46  21.91,31.11 90 top
R47  23.5,31.11 90 top
R48  26.35,31.11 270 top
R49  29.53,31.11 270 top
R50  31.11,31.11 90 top
R51  34.92,31.11 270 top
R52  38.1,31.11 270 top
R53  39.69,31.11 90 top
R54  45.72,31.11 90 top
R55  47.31,31.11 90 top
R56  53.02,31.11 90 top
R57  54.61,31.11 90 top
R58  58.42,31.11 270 top
R59  61.59,31.11 270 top
R60  63.18,31.11 90 top
R61  66.67,31.11 270 top
R62  69.85,31.11 270 top
R63  71.44,31.11 90 top
R64  78.11,31.11 90 top
R65  12.7,43.5 90 top
SW1  20.95,97.79 180 top
SW2  20.95,88.9 180 top
SW3  9.53,71.12 90 top
SW4  9.53,54.61 90 top
SW5  7.62,34.29 0 top
U$1  [EURORACK_TEMPLATE]  not placed on the board
U$3  [ROHS_BIG]  88.9,32.7 0 bottom
UC1  30.48,69.85 270 top

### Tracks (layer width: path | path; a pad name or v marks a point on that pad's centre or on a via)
+3V3  (via drill 0.6)
  Top 0.254: SW1.B' SW1.B 24.13,95.56 v24.13,93.03 | UC1.36 36.62,72.6 C3.1 36.93,72.71 37.47,72.71 v38.1,73.34 | UC1.24 33.23,64.88 33.26,64.85 33.73,64.85 | 33.97,63.82 33.76,63.82 C10.1 33.66,64.77 33.73,64.85 | v34.29,65.41 33.73,64.85 | v38.1,79.38 38.1,80.64 39.05,81.6 JP4.1 | R10.2 25.51,72.6 UC1.1 26.41,72.78 C2.1 | C2.1 26.53,74.1 UC1.48 | C2.1 26.35,74.03 | v33.02,68.58 33.02,70.17 31.11,72.07 28.1,72.07 26.41,73.76 C2.1 | v24.77,77.47 26.41,75.83 C2.1 | v38.1,68.58 38.1,67.31 41.27,64.14 45.72,64.14 49.63,68.05 C6.1
  Top 0.406: IC1.2 59.03,69.83 57.15,67.94 56.02,67.94 C5.+ 52.32,67.8 C6.1 51.97,67.94
  Bottom 0.254: v34.29,65.41 33.02,66.67 v33.02,68.58 v38.1,68.58 v38.1,73.34 38.1,75.56 38.73,76.2 38.73,78.74 v38.1,79.38 | v24.77,77.47 24.13,78.11 v24.13,93.03
+3V3_A  (via drill 0.6)
  Top 0.254: C14.1 IC3.1 34.56,56.15 | R17.1 51.97,57.15 51.44,57.15 50.8,56.52 50.8,54.61 51.44,53.98 | C7.1 23.81,67.25 23.81,67.94 24.47,68.6 UC1.9
  Top 0.305: 51.44,53.98 50.8,53.98 49.53,55.24 49.53,56.52 48.26,57.78 40.01,57.78 38.73,56.52 34.92,56.52 34.56,56.15 | C16.1 51.97,53.76 | D3.2 73.17,50.16 58.42,50.16 55.88,52.7 C15.+ 56.02,53.83 58.42,51.44 66.67,51.44 68.58,53.34 v68.58,60.01 | v69.22,69.53 71.12,71.44 71.12,76.2 73.66,78.74 79.38,78.74 80.64,80.01 80.64,86.31 R5.P$1 80.61,87.67 78.42,89.85 57.78,89.85 | v12.06,90.49 12.7,89.85 34.92,89.85 | 57.78,89.85 v57.78,90.17 | 57.78,89.85 34.92,89.85 | 34.92,89.85 v34.92,90.17 | C13.1 31.81,54.93 29.53,54.93 28.57,53.98 25.72,53.98 v25.4,53.66 | C7.1 C8.1 23.71,64.35 v23.5,64.14
  Top 0.406: C13.1 C14.1 | IC4.2 59.03,55.85 57.15,53.98 56.02,53.98 C15.+ 55.81,53.76 C16.1 51.85,53.98 51.44,53.98 48.9,53.98 46.99,55.88 46.33,55.88 R14.P$1
  Bottom 0.305: v69.22,69.53 68.58,68.9 v68.58,60.01 | R2.P$1 12.06,86.39 v12.06,90.49 | R4.P$1 57.78,86.39 v57.78,90.17 | R3.P$1 34.92,86.39 v34.92,90.17 | v25.4,53.66 25.4,59.69 23.5,61.59 v23.5,64.14
ADD_SWITCH  (via drill 0.6)
  Top 0.254: SW3.A1 SW3.A2 | v6.99,61.59 7.62,61.59 9.53,59.69 9.53,56.2 10.48,55.24 28.1,55.24 29.69,56.83 29.69,58.58 31.73,60.62 UC1.21
  Bottom 0.254: SW3.A1 6.99,68.58 v6.99,61.59
AREF_2.5
  Top 0.254: C12.1 51.97,60.64 51.12,60.64 48.9,58.42 39.69,58.42 39.05,57.78 36.51,57.78 36.06,58.24 IC3.7 | C12.1 R17.2 | C12.1 52.14,60.81 IC2.1
AREF_5
  Top 0.254: IC6.2 7.94,42.17 IC6.1 5.97,42.17 5.08,41.27 JP1.1
AREF_10
  Top 0.254: IC6.7 IC6.6 9.84,48.58 10.16,48.9 13.34,48.9 14.61,47.62 14.61,40.01 13.34,38.73 JP1.3
AREF_10_0
  Top 0.254: R27.2 11.27,47.52 IC6.5 11.11,46.04 10.94,45.87 IC5.1 5.54,46.04 5.4,46.04 4.23,47.2 R26.2
BOOT_FLASH  (via drill 0.6)
  Top 0.254: SW1.A' SW1.A 25.18,98.96 R1.2 25.18,97.37 25.72,96.84 26.19,96.84 26.35,96.68 26.35,94.93 25.4,93.98 v25.4,92.39 | v25.4,80.8 26.83,80.8 29.73,77.9 UC1.44
  Bottom 0.254: v25.4,80.8 24.77,81.44 24.77,91.76 v25.4,92.39
DAC_MOSI
  Top 0.254: IC3.8 35.56,62.23 37.47,64.14 37.47,66.99 35.86,68.6 UC1.28
DAC_SCK
  Top 0.254: UC1.26 34.7,67.63 33.81,67.63 33.5,67.31 33.5,66.83 33.81,66.52 35.4,66.52 36.51,65.41 36.51,64.77 34.56,62.82 IC3.10
DAC_SS
  Top 0.254: IC3.9 35.08,59.29 35.08,62.55 36.99,64.45 36.99,66.52 36.41,67.1 UC1.25
DEL_SWITCH
  Top 0.254: SW4.A1 7.03,54.61 | 7.03,54.61 SW4.A2 | UC1.22 32.23,60.33 30.16,58.26 30.16,56.52 28.26,54.61 7.03,54.61
FB_CURRENT
  Top 0.254: R54.2 R55.2 47.31,33.34 46.99,33.66 IC10.2
FB_CURRENT1
  Top 0.254: R33.2 R34.2 47.31,41.59 46.99,41.27 IC10.15
FB_CURRENT2
  Top 0.254: IC10.10 53.34,41.27 53.02,41.59 R35.2 R36.2
FB_CURRENT3
  Top 0.254: R57.2 R56.2 53.02,33.34 53.34,33.66 IC10.7
FRAME_CHANGE  (via drill 0.6)
  Top 0.254: UC1.16 29.21,65.58 29.21,64.14 28.57,63.5 28.57,59.05 29.21,58.42 29.21,57.15 27.94,55.88 20.64,55.88 v20.32,56.2 | R23.1 v20.32,52.7
  Bottom 0.254: v20.32,52.7 v20.32,56.2
GAIN_1  (via drill 0.6)
  Top 0.254: R19.2 C17.1 32.7,49.21 33.34,48.58 37.94,48.58 38.89,47.62 41.27,47.62 42.55,46.35 42.55,41.27 42.55,40.96 v41.91,40.32 | v42.55,36.2 42.86,36.51 47.94,36.51 48.26,36.2 IC10.3
  Bottom 0.254: v42.55,36.2 42.55,39.05 42.55,39.69 v41.91,40.32
GAIN_2
  Top 0.254: IC10.14 48.26,41.27 48.9,41.91 49.53,41.91 49.85,42.23 49.85,46.67 48.26,48.26 39.21,48.26 38.42,49.05 36.04,49.05 35.88,49.21 C18.1 R20.2
GAIN_3
  Top 0.254: IC10.11 52.07,41.43 51.59,41.91 50.8,41.91 50.48,42.23 50.48,46.99 48.58,48.9 39.37,48.9 39.05,49.21 C19.1 R21.2
GAIN_4  (via drill 0.6)
  Top 0.254: IC10.6 52.07,36.2 52.39,36.51 57.15,36.51 v57.47,36.2 | v57.78,41.27 57.78,46.99 55.3,49.47 43.71,49.47 43.18,50.01 42.44,50.01 C20.1 R22.2
  Bottom 0.254: v57.47,36.2 57.47,40.01 57.78,40.32 v57.78,41.27
GATE2_LED
  Top 0.254: LED3.A 53.12,82.77 R8.2
GATE3_LED
  Top 0.254: LED2.A 32.38,83.19 34.29,83.19 34.71,82.77 R7.2
GATE4_LED
  Top 0.254: LED1.A 9.53,80.64 11.43,80.64 11.85,81.06 R6.2
GND  (via drill 0.6)
  Top 0.254: UC1.35 33.66,72.1 33.66,72.07 v32.7,72.07 | 28.26,74.1 UC1.47 28.26,74.13 28.26,75.88 v27.3,76.83 | UC1.20 31.23,66.47 | C10.2 33.55,61.91 33.02,61.91 32.73,62.2 UC1.23 | C7.2 21.91,67.25 21.91,67.94 23.06,69.1 UC1.8
  other vias: 81.28,52.07 74.3,71.12 65.41,60.96 60.33,46.35 68.58,46.35 73.66,43.81 73.98,35.56 66.04,35.56 56.2,46.35 44.13,46.35 36.83,46.35 28.26,46.35 16.51,41.59 26.04,35.56 42.55,34.61 76.83,37.78 21.59,37.47 35.24,34.77 48.26,46.35 52.07,46.35 39.05,53.02 35.88,53.02 32.7,53.02 52.07,64.14 53.98,57.78 53.98,71.75 16.51,70.48 35.24,74.61 30.16,67.63 41.59,41.91 21.59,80.01 20.95,90.81 29.21,90.81 27.94,87 33.34,60.33 29.84,53.66 28.73,69.69 23.81,75.41 29.84,25.72 33.34,25.72 39.37,26.04 47.62,26.04 62.23,26.04 54.93,26.04 72.07,26.04 79.38,28.57 42.39,53.02 48.26,52.7 50.16,31.11 59.05,35.56 50.16,37.47 34.29,40.01 66.04,40.01 38.1,38.1 38.1,59.69 1.27,55.88 5.08,100.33 35.56,100.33 45.72,100.33 55.88,100.33 66.04,100.33 76.2,100.33 87.63,86.36 87.63,15.24 87.63,5.08 1.27,25.4 1.27,66.04 1.27,15.24 15.24,1.27 25.4,1.27 45.72,1.27 55.88,1.27 76.2,1.27 1.27,76.2 1.27,86.36 1.27,96.52 87.63,96.52 16.51,35.56 42.07,26.04 29.84,37.15 69.85,37.47 66.04,86.36 45.72,86.36 21.27,82.87 26.67,83.82 62.55,70.8 62.55,69.22 58.1,72.39 64.14,70.8 64.14,72.39 62.55,54.93 62.55,56.52 62.55,58.1 60.33,60.01 64.14,69.22 62.55,67.63 64.14,67.63 62.55,66.04 12.7,41.27 1.27,45.72
  pour Bottom: 0,101.6 0,0 88.9,0 88.9,101.6
  pour Top (isolate 0.203): 0,101.6 0,0 88.9,0 88.9,101.6
IN_1  (via drill 0.6)
  Top 0.254: R54.1 45.62,30.16 v44.29,30.16 | v17.46,17.78 17.78,18.1 43.34,18.1 v43.66,17.78
  Bottom 0.254: v44.29,30.16 43.81,29.69 43.81,25.72 44.13,25.4 44.13,22.86 43.18,21.91 43.18,18.26 v43.66,17.78 | J2.TIP 17.46,20.92 v17.46,17.78
IN_2  (via drill 0.6)
  Top 0.254: R33.1 45.72,45.72 v46.35,46.35 | v44.77,19.68 43.97,19.68 43.5,20.16 41.91,21.75 40.64,23.02 38.73,23.02 36.67,20.95 J3.TIP
  Bottom 0.254: v46.35,46.35 46.35,23.5 44.77,21.91 v44.77,19.68
IN_3  (via drill 0.6)
  Top 0.254: J4.TIP 47.27,21.59 v51.75,21.59 | v53.98,46.35 54.61,45.72 R36.1
  Bottom 0.254: v51.75,21.59 53.98,23.81 v53.98,46.35
IN_4  (via drill 0.6)
  Top 0.254: R57.1 54.71,30.16 v56.04,30.16 | v56.52,20.95 J5.TIP
  Bottom 0.254: v56.04,30.16 56.52,29.69 56.52,23.81 56.2,23.5 56.2,21.91 56.52,21.59 v56.52,20.95
JTCK  (via drill 0.6)
  Top 0.254: v40.64,76.52 40.32,76.83 34.77,76.83 33.23,75.3 UC1.37
  Bottom 0.254: v40.64,76.52 40.01,77.15 40.01,79.06 40.64,79.69 JP4.4
JTDI
  Top 0.254: JP4.8 43.18,79.06 41.59,77.47 34.61,77.47 32.73,75.59 UC1.38
JTDO
  Top 0.254: JP4.6 41.91,79.06 40.96,78.11 34.45,78.11 32.23,75.89 UC1.39
JTMS  (via drill 0.6)
  Top 0.254: v39.37,74.93 39.37,73.34 37.63,71.6 UC1.34
  Bottom 0.254: v39.37,74.93 JP4.2
LED_B  (via drill 0.6)
  Top 0.254: v30.16,60.96 29.84,61.28 29.84,62.87 30.23,63.25 UC1.18 | v43.81,66.36 R12.1
  Bottom 0.254: v30.16,60.96 31.11,60.96 32.38,62.23 34.92,62.23 39.37,66.67 43.5,66.67 v43.81,66.36
LED_CH1
  Top 0.254: R6.1 12.8,82.87 18.41,82.87 20.32,80.96 22.54,80.96 24.29,79.22 26.83,79.22 28.73,77.31 UC1.46
LED_CH2
  Top 0.254: R7.1 | R7.1 35.56,80.33 35.24,80.01 28.57,80.01 26.67,81.92 25.08,81.92 24.45,81.28 24.45,80.17 24.92,79.69 27.15,79.69 29.23,77.61 UC1.45
LED_CH3
  Top 0.254: R8.1 51.97,80.96 48.26,80.96 45.4,83.82 37.78,83.82 36.51,82.55 36.51,80.01 35.88,79.38 31.43,79.38 30.23,78.17 UC1.43
LED_CH4
  Top 0.254: R9.1 74.83,80.96 58.42,80.96 57.47,80.01 51.12,80.01 50.8,80.33 47.94,80.33 45.09,83.19 38.1,83.19 37.15,82.23 37.15,79.69 36.2,78.74 31.75,78.74 30.73,77.72 UC1.42
LED_FRAME  (via drill 0.6)
  Top 0.254: R16.1 14.61,60.96 13.97,61.59 12.38,61.59 8.57,65.41 8.57,75.88 6.67,77.79 6.67,81.92 9.21,84.45 13.02,84.45 13.97,83.5 18.73,83.5 20.64,81.6 23.81,81.6 24.77,82.55 26.99,82.55 28.89,80.64 32.07,80.64 v32.38,80.96 | v32.38,77.79 31.23,76.63 UC1.41
  Bottom 0.254: v32.38,80.96 v32.38,77.79
LED_G  (via drill 0.6)
  Top 0.254: v41.91,65.72 R11.1 | v29.53,59.69 29.21,60.01 29.21,63.18 29.73,63.7 UC1.17
  Bottom 0.254: v41.91,65.72 41.59,66.04 39.69,66.04 35.24,61.59 32.7,61.59 30.8,59.69 v29.53,59.69
LED_R  (via drill 0.6)
  Top 0.254: v45.72,67.31 R13.1 | v30.8,62.23 30.73,62.3 UC1.19
  Bottom 0.254: v30.8,62.23 31.43,62.23 32.07,62.87 34.61,62.87 39.05,67.31 v45.72,67.31
MODULATION  (via drill 0.6)
  Top 0.254: v45.09,51.12 55.24,51.12 58.74,47.62 74.12,47.62 D3.3 74.3,46.67 75.56,45.4 R39.1 | v27.3,51.44 28.89,49.85 28.89,48.9 30.48,47.31 37.47,47.31 39.05,45.72 40.32,45.72 v40.96,45.09 | UC1.14 28.23,64.74 27.3,63.82 27.3,58.74 v26.99,58.42
  Bottom 0.254: v45.09,51.12 45.09,49.21 v40.96,45.09 | v27.3,51.44 27.3,53.34 27.62,53.66 27.62,56.83 27.3,57.15 27.3,58.1 v26.99,58.42
N$1
  Top 0.254: R64.2 IC13.2 78.11,36.2 78.42,36.51 81.92,36.51 83.82,38.42 83.82,46.99 82.87,47.94 80.01,47.94 78.11,49.85 78.11,55.83 R15.P$1
N$2
  Top 0.254: R55.1 C42.1
N$3
  Top 0.254: 17.36,44.77 R28.2 17.46,47.94 15.24,50.16 7.62,50.16 6.35,48.9 3.81,48.9 3.17,48.26 3.17,46.99 2.54,46.35 2.54,38.1 5.4,35.24 5.4,26.99 1.27,22.86 1.27,17.78 2.82,16.23 J7.TIP
N$4  (via drill 0.6)
  Top 0.254: IC9.7 38.1,44.45 38.42,44.77 38.95,44.77 R32.2 39.79,44.66 40.64,43.81 v40.64,43.18 | R53.1 39.69,29.21 v40.01,28.89
  Bottom 0.254: v40.01,28.89 39.69,29.21 39.69,42.23 v40.64,43.18
N$5
  Top 0.254: R15.P$2 75.56,56.83 76.2,57.47 79.06,57.47 80.64,55.88 R18.2
N$6
  Top 0.254: LED4.A 75.98,82.77 R9.2
N$7
  Top 0.254: UC1.5 19.25,70.6 18.41,71.44 Q1.2 15.81,76.58 14.92,77.47 C1.2
N$8
  Top 0.254: UC1.6 18.98,70.1 18.41,69.53 Q1.1 15.81,66.93 14.92,66.04 C9.2
N$9
  Top 0.254: R64.1 78,30.16 77.47,30.16 76.83,30.8 IC13.1 76.83,36.2 77.79,37.15 81.6,37.15 83.19,38.73 83.19,46.67 82.55,47.31 80.96,47.31 80.33,46.67 R41.2
N$10
  Top 0.254: C27.1 53.02,44.55 R35.1
N$11  (via drill 0.6)
  Top 0.254: R18.1 80.54,53.66 79.69,53.66 78.74,52.7 78.74,50.16 80.33,48.58 83.19,48.58 84.45,47.31 84.45,26.67 v83.82,26.04 | J6.TIP v81.6,20.95
  Bottom 0.254: v83.82,26.04 81.92,24.13 81.92,21.27 v81.6,20.95
N$12
  Top 0.254: IC10.4 49.53,36.2 48.58,37.15 32.38,37.15 30.8,38.73 IC8.6 R31.1
N$13
  Top 0.254: IC13.7 78.11,41.27 78.74,41.91 R40.1 C31.2 R39.2
N$14
  Top 0.254: R15.P$3 73.03,55.83 73.03,54.61 73.66,53.98 76.83,53.98 77.47,53.34 77.47,49.53 78.74,48.26 R40.2 | R41.1 R42.1 | IC13.6 79.38,41.27 80.33,42.23 R41.1 | R41.1 78.74,44.55 R40.2 | R40.2 C31.1
N$15
  Top 0.254: R49.1 R50.2 | C39.1 R49.1 | R49.1 IC8.2
N$16
  Top 0.254: R49.2 C39.2 26.35,31.85 R48.1 26.35,32.7 26.67,33.02 27.62,33.02 28.26,33.66 IC8.1
N$17
  Top 0.254: IC7.7 19.68,41.27 19.05,41.91 17.78,41.91 17.46,42.23 R28.1 19.05,44.55 C23.2 R29.2
N$18
  Top 0.254: C22.1 47.31,44.55 R34.1
N$19
  Top 0.254: R44.2 R43.1 C38.1 | R44.2 R45.2 R46.2 R47.2 | IC7.2 19.68,33.66 18.73,32.7 R44.2
N$20
  Top 0.254: IC10.13 49.53,38.73 49.21,38.42 39.69,38.42 39.37,38.73 IC9.6 39.37,41.27 39.05,41.59 R32.1
N$21
  Top 0.254: IC7.6 20.95,41.59 20.64,41.91 R29.1 | R29.1 R30.2 | R29.1 C23.1
N$22
  Top 0.254: R52.1 R53.2 | C40.1 R52.1 | R52.1 IC9.2
N$23
  Top 0.254: R52.2 C40.2 34.92,31.85 R51.1 34.92,32.7 35.24,33.02 36.2,33.02 36.83,33.66 IC9.1
N$24
  Top 0.254: IC10.12 50.8,38.73 51.12,38.42 62.55,38.42 62.87,38.73 IC11.6 R37.1
N$25
  Top 0.254: R16.2 18.41,60.96 19.68,62.23 LED6.A
N$26
  Top 0.254: R59.1 R60.2 | R59.1 IC11.2 | C44.1 R59.1
N$27
  Top 0.254: R59.2 C44.2 58.42,31.85 R58.1 58.42,32.7 58.74,33.02 59.69,33.02 60.33,33.66 IC11.1
N$28
  Top 0.254: R56.1 C43.1
N$29
  Top 0.254: R30.1 22.96,44.66 23.18,44.45 23.18,42.23 22.86,41.91 21.91,41.91 21.59,41.59 21.59,38.73 21.27,38.42 20.64,38.42 18.41,36.2 IC7.1 18.36,34.87 18.41,34.8 18.41,33.66 17.78,33.02 14.92,33.02 14.61,32.7 14.61,30.48 14.82,30.27 C38.2 R43.2
N$30
  Top 0.254: IC10.5 50.8,36.2 51.75,37.15 67.31,37.15 68.58,38.42 70.8,38.42 71.12,38.73 IC12.6 R38.1
N$31
  Top 0.254: R27.1 R65.2 10.69,44.35 9.84,43.5 IC6.3
N$32
  Top 0.254: R62.1 IC12.2 | R62.1 R63.2 | C46.1 R62.1
N$33
  Top 0.254: R62.2 C46.2 66.67,31.85 R61.1 66.67,32.7 66.99,33.02 67.94,33.02 68.58,33.66 IC12.1
N$34
  Top 0.254: SW5.P 7.62,30.48 10.92,27.18 J1.SW
N$35
  Top 0.254: R13.2 LED5.RED
N$36
  Top 0.254: R12.2 43.18,71.65 LED5.BLU
N$37
  Top 0.254: R11.2 LED5.GRN
N$39
  Top 0.254: R19.1 31.11,53.34 31.75,53.98 34.61,53.98 35.06,54.43 IC3.2
N$40  (via drill 0.6)
  Top 0.254: J8.TIP 17.46,6.39 17.46,11.43 20,13.97 24.77,13.97 v26.99,16.19 | v26.99,28.89 26.35,29.53 R48.2
  Bottom 0.254: v26.99,16.19 27.3,16.51 27.3,26.67 27.3,26.99 26.99,27.3 v26.99,28.89
N$41
  Top 0.254: R20.1 34.29,52.86 35.56,54.13 IC3.3
N$42
  Top 0.406: JP1.2 7.62,37.47 8.57,36.51 11.11,36.51 12.32,35.31 SW5.S
N$43
  Top 0.254: R21.1 37.47,52.7 36.06,54.11 IC3.4
N$44  (via drill 0.6)
  Top 0.254: R25.1 R24.2 25.61,49.85 24.77,49.85 24.62,49.99 Q2.C 23.43,49.74 23.18,49.49 23.18,45.4 23.81,44.77 23.81,41.91 23.18,41.27 v23.18,38.1 | v25.08,12.38 25.08,9.84 31.43,3.49 74.61,3.49 75.84,4.72 J12.TIP
  Bottom 0.254: v23.18,38.1 23.18,28.89 23.81,28.26 23.81,25.08 22.23,23.5 22.23,20 25.08,17.14 v25.08,12.38
N$45
  Top 0.254: R22.1 40.64,52.7 39.37,53.98 37.15,53.98 36.56,54.56 IC3.5
N$47
  Top 0.254: R23.2 20.57,47.8 Q2.B
N$48
  Top 0.254: IC12.7 69.85,44.13 70.48,44.77 71.02,44.77 R38.2 71.86,44.66 72.07,44.45 72.07,42.23 71.75,41.91 71.75,33.34 72.39,32.7 72.39,30.48 72.07,30.16 71.54,30.16 R63.1
N$49  (via drill 0.6)
  Top 0.254: v33.66,16.19 32.03,14.57 J9.TIP | v33.5,29.37 34.39,30.27 R51.2
  Bottom 0.254: v33.5,29.37 34.29,28.57 34.29,18.1 33.66,17.46 v33.66,16.19
N$50  (via drill 0.6)
  Top 0.254: v69.22,17.14 69.22,15.56 67.63,13.97 64.77,13.97 61.24,10.44 J11.TIP | v67.47,28.73 66.67,29.53 R61.2
  Bottom 0.254: v69.22,17.14 67.47,18.89 | 67.47,18.89 | 67.47,18.89 v67.47,28.73
N$51  (via drill 0.6)
  Top 0.254: v58.74,17.78 54.93,13.97 50.8,13.97 46.63,9.8 J10.TIP | v58.74,28.57 58.42,28.89 R58.2
  Bottom 0.254: v58.74,17.78 v58.74,28.57
N$56
  Top 0.406: JP2.2 JP2.1 86.49,76.97 P1.2
N$64
  Top 0.406: JP2.10 JP2.9 86.49,65.28 P2.2
PAN
  Top 0.254: J1.TIP 2.86,20.92 2.86,19.05 3.17,18.73 25.4,18.73 | 25.4,18.73 40.01,18.73 | 40.01,18.73 54.61,18.73 | 54.61,18.73 68.26,18.73 69.34,19.81 J5.SW | J4.SW 54.61,20.83 54.61,18.73 | J3.SW 40.01,20.83 40.01,18.73 | J2.SW 25.4,20.83 25.4,18.73
POT_CH1
  Top 0.254: UC1.10 25.24,68.1 24.87,67.73 24.87,62.02 22.54,59.69 14.92,59.69 13.65,60.96 12.06,60.96 5.4,67.63 5.4,81.6 9.53,85.72 R2.P$2
POT_CH2
  Top 0.254: R3.P$2 32.38,87.31 31.75,87.95 5.71,87.95 4.76,87 4.76,67.31 11.75,60.33 13.34,60.33 14.61,59.05 22.86,59.05 25.35,61.54 25.35,67.42 25.53,67.6 UC1.11
POT_CH3
  Top 0.254: R4.P$2 55.24,87.31 53.98,88.58 5.4,88.58 4.13,87.31 4.13,66.99 11.43,59.69 13.02,59.69 14.29,58.42 23.18,58.42 25.88,61.12 25.88,66.75 UC1.12
POT_CH4
  Top 0.254: R5.P$2 78.11,87.63 76.52,89.22 5.08,89.22 3.49,87.63 3.49,66.67 11.11,59.05 12.7,59.05 13.97,57.78 23.5,57.78 26.35,60.64 26.35,64.45 27.5,65.6 UC1.13
POT_FRAME  (via drill 0.6)
  Top 0.254: v43.81,53.18 R14.P$2 | v40.96,46.67 38.89,46.67 37.62,47.94 30.8,47.94 29.53,49.21 29.53,50.01 28.26,51.28 v28.26,52.39 | UC1.15 28.73,64.45 27.94,63.66 27.94,58.1 v28.26,57.78
  Bottom 0.254: v43.81,53.18 44.13,52.86 44.13,49.21 41.59,46.67 v40.96,46.67 | v28.26,52.39 v28.26,57.78
RESET  (via drill 0.6)
  Top 0.254: SW2.B 24.45,87 26.04,87 28.57,84.45 45.4,84.45 v45.72,84.77 | v22.86,83.66 24.36,85.16 SW2.B | v20.95,69.22 21.34,69.6 UC1.7 | v20.95,71.75 R10.1 22.86,71.86 v22.86,78.11 | SW2.B SW2.B'
  Bottom 0.254: v22.86,78.11 23.65,78.9 23.65,82.87 v22.86,83.66 | v20.95,69.22 v20.95,71.75 | JP4.10 45.09,80.33 45.72,80.96 v45.72,84.77
RX
  Top 0.254: UC1.31 36.92,70.1 41.75,74.93 58.42,74.93 59.69,76.2 JP3.4
TX
  Top 0.254: UC1.30 37.22,69.6 41.91,74.3 60.33,74.3 62.23,76.2 JP3.5
VCA0_1
  Top 0.254: R31.2 30.06,44.66 29.53,44.13 IC8.7 29.53,38.73 31.43,36.83 31.43,33.34 32.07,32.7 32.07,30.48 31.75,30.16 31.22,30.16 R50.1
VCA0_3  (via drill 0.6)
  Top 0.254: IC11.7 61.59,44.13 62.23,44.77 62.76,44.77 R37.2 63.6,44.66 64.45,43.81 v64.45,42.55 | R60.1 63.18,29.21 v62.55,28.57
  Bottom 0.254: v62.55,28.57 63.18,29.21 63.18,41.27 v64.45,42.55
VCA_1  (via drill 0.6)
  Top 0.254: R44.1 18.73,29.53 14.92,25.72 v14.92,21.59 | v14.92,15.88 14.92,5.4 16.51,3.81 24.13,3.81 25.52,5.21 J8.SW
  Bottom 0.254: v14.92,15.88 v14.92,21.59
VCA_2  (via drill 0.6)
  Top 0.254: R47.1 23.5,29.53 25.08,27.94 34.61,27.94 34.92,28.26 35.24,28.26 37.78,28.26 v38.1,28.57 | v40.01,15.88 40.13,15.75 J9.SW
  Bottom 0.254: v38.1,28.57 38.42,28.26 38.42,24.13 38.1,23.81 38.1,19.37 40.01,17.46 v40.01,15.88
VCA_3  (via drill 0.6)
  Top 0.254: R46.1 21.91,29.53 22.23,29.21 22.86,29.21 24.77,27.3 34.92,27.3 35.24,27.62 48.58,27.62 v48.9,27.94 | v48.9,17.78 45.09,13.97 45.09,4.76 45.72,4.13 53.34,4.13 54.73,5.52 J10.SW
  Bottom 0.254: v48.9,17.78 v48.9,27.94
VCA_4  (via drill 0.6)
  Top 0.254: v70.8,27.3 70.48,26.99 36.2,26.99 35.56,26.99 35.24,26.67 24.45,26.67 22.54,28.57 21.27,28.57 20.32,29.53 R45.1 | v71.12,18.41 71.12,9.14 69.34,7.36 J11.SW
  Bottom 0.254: v70.8,27.3 70.8,23.5 71.12,23.18 v71.12,18.41
VCC  (via drill 0.6)
  Top 0.254: R25.2 27.3,43.18 27.52,42.97 C24.1
  Top 0.305: IC6.8 7.3,48.9 7.94,49.53 13.65,49.53 15.24,47.94 15.24,38.1
  Top 0.406: 72.39,69.85 72.39,74.93 73.66,76.2 76.06,76.2 C4.+ 76.34,76.2 78.74,76.2 81.92,79.38 82.55,79.38 | IC4.3 63.09,53.57 64.45,54.93 64.45,58.1 60.81,61.74 C11.+ | 72.39,69.85 77.47,64.77 77.47,61.28 83.82,54.93 83.82,48.9 85.41,47.31 85.41,26.04 83.5,24.13 75.25,24.13 | 45.72,40.32 IC10.16 44.19,40.06 v44.13,40.01 C26.1 | v17.78,26.04 19.68,24.13 28.26,24.13 | 28.26,24.13 35.24,24.13 | 35.24,24.13 v35.24,24.45 | 35.24,24.13 37.47,24.13 38.1,24.77 v43.18,24.77 43.81,24.13 60.33,24.13 | 60.33,24.13 69.22,24.13 | 28.26,24.13 v28.26,24.77 | IC8.8 C24.1 27.73,42.97 27.3,42.55 27.3,38.73 v28.26,37.78 | 60.33,24.13 v60.33,24.77 | IC11.8 C29.1 60.22,42.86 59.69,42.86 59.37,42.55 59.37,40.64 59.05,40.32 v59.05,39.37 | 69.22,24.13 v69.22,25.4 | IC12.8 C30.1 68.05,42.97 67.31,42.23 v67.31,39.37 | 72.39,69.85 67.63,65.09 63.18,65.09 60.96,62.87 C11.+ | 82.55,79.38 P1.1 | D1.C 82.55,79.38 | IC9.8 C25.1 36.3,42.97 35.56,42.23 v35.56,39.37 | IC1.3 60.81,67.07 C11.+ | 18.41,40.64 IC7.8 18.41,38.73 17.78,38.1 16.61,38.1 C35.1 16.41,38.1 15.24,38.1 v15.24,36.51 | 76.78,40.01 IC13.8 75.84,40.06 C34.1 75.56,38.73 75.25,38.42 75.25,24.13 | 69.22,24.13 75.25,24.13 | R26.1 7.3,47.62 IC6.8
  Bottom 0.406: v17.78,26.04 15.24,28.57 v15.24,36.51 | v28.26,24.77 v28.26,37.78 | v35.24,24.45 35.24,27.94 36.51,29.21 36.51,38.42 v35.56,39.37 | v43.18,24.77 43.18,33.02 44.13,33.97 v44.13,40.01 | v60.33,24.77 60.33,38.1 v59.05,39.37 | v67.31,39.37 67.31,31.75 69.22,29.84 v69.22,25.4
VEE  (via drill 0.6)
  Top 0.254: v81.92,46.35 R42.2 | 86.36,46.35 v87,46.35
  Top 0.305: IC6.4 11.11,40.96 12.38,39.69 v12.7,39.69 | v23.81,22.86 23.5,23.18 19.37,23.18 17.78,24.77 17.14,24.77 16.51,25.4 v16.19,25.4
  Top 0.406: P2.1 82.56,61.73 D2.A 82.55,59.37 86.36,55.56 86.36,50.16 | 29.21,23.18 24.13,23.18 v23.81,22.86 | 29.21,23.18 37.62,23.18 38.26,23.81 41.43,23.81 v42.07,23.18 57.15,23.18 | 57.15,23.18 64.45,23.18 | 64.45,23.18 73.66,23.18 | 73.66,23.18 78.11,23.18 | 78.11,23.18 84.14,23.18 86.36,25.4 86.36,46.35 86.36,50.16 | 57.15,23.18 v57.15,22.54 | v55.88,40.01 56.2,40.32 56.2,41.91 | 56.2,41.91 C28.2 | 64.77,33.02 64.14,33.66 IC11.4 | 64.77,33.02 C45.2 | v65.09,33.34 64.77,33.02 | 64.45,23.18 v64.45,22.54 | IC12.4 72.39,33.97 73.34,33.02 | v73.66,33.34 73.34,33.02 | 73.66,23.18 v73.66,22.54 | 73.34,33.02 C47.2 | 78.11,23.18 v78.11,22.54 | IC13.4 C48.2 81.38,31.96 81.92,31.43 81.92,29.21 v78.11,25.4 | 29.21,23.18 v29.21,22.54 | 41.27,33.02 C41.2 | v41.59,33.34 41.27,33.02 | IC9.4 40.64,33.66 41.27,33.02 | 86.36,50.16 C21.- | 54.67,40.01 IC10.9 54.61,41.27 55.24,41.91 56.2,41.91 | IC7.4 22.29,34.87 22.86,34.29 23.71,34.29 C37.2 23.91,34.29 24.45,34.29 v25.08,33.66 | v33.02,33.02 33.66,33.66 C36.2 33.44,34.61 32.7,34.61 32.45,34.87 IC8.4
  Bottom 0.254: v87,46.35 v81.92,46.35
  Bottom 0.305: v12.7,39.69 13.97,38.42 13.97,35.88 14.61,35.24 14.61,27.94 16.19,26.35 v16.19,25.4
  Bottom 0.406: v55.88,40.01 55.88,34.29 57.15,33.02 v57.15,22.54 | v64.45,22.54 64.45,32.7 v65.09,33.34 | v73.66,22.54 v73.66,33.34 | v78.11,22.54 v78.11,25.4 | v25.08,33.66 25.08,24.13 v23.81,22.86 | v29.21,22.54 31.43,24.77 31.43,31.43 v33.02,33.02 | 41.43,33.18 v41.59,33.34 | 41.43,33.18 41.43,29.84 41.91,29.37 41.91,28.26 40.96,27.3 40.96,24.13 41.91,23.18 v42.07,23.18 | 41.43,33.18

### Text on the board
tPlace: Frames
bPlace: Frames | Red | stripe | +5V | +10V
tNames: SYSBOOT | RESET | cc-by-sa Émilie Gillet, 2013. v0.3
bNames: cc-by-sa Émilie Gillet, 2013. v0.3 | mini JTAG | JTMS | JTCK | JTDO | JTDI | RESET | FTDI dongle | +12V | GND | RX< | TX> | GND | GND | GND | -12V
